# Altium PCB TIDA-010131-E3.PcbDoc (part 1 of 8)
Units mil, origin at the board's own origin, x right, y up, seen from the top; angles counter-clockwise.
Board outline 6889.76 x 5118.11 mil, 6 copper layers (Top Layer, GND Layer, Signal Layer 1, Signal Layer 2, PWR Layer, Bottom Layer), stack 58.5 mil thick; 758 components, 455 nets, 2194 pads, 1156 vias.
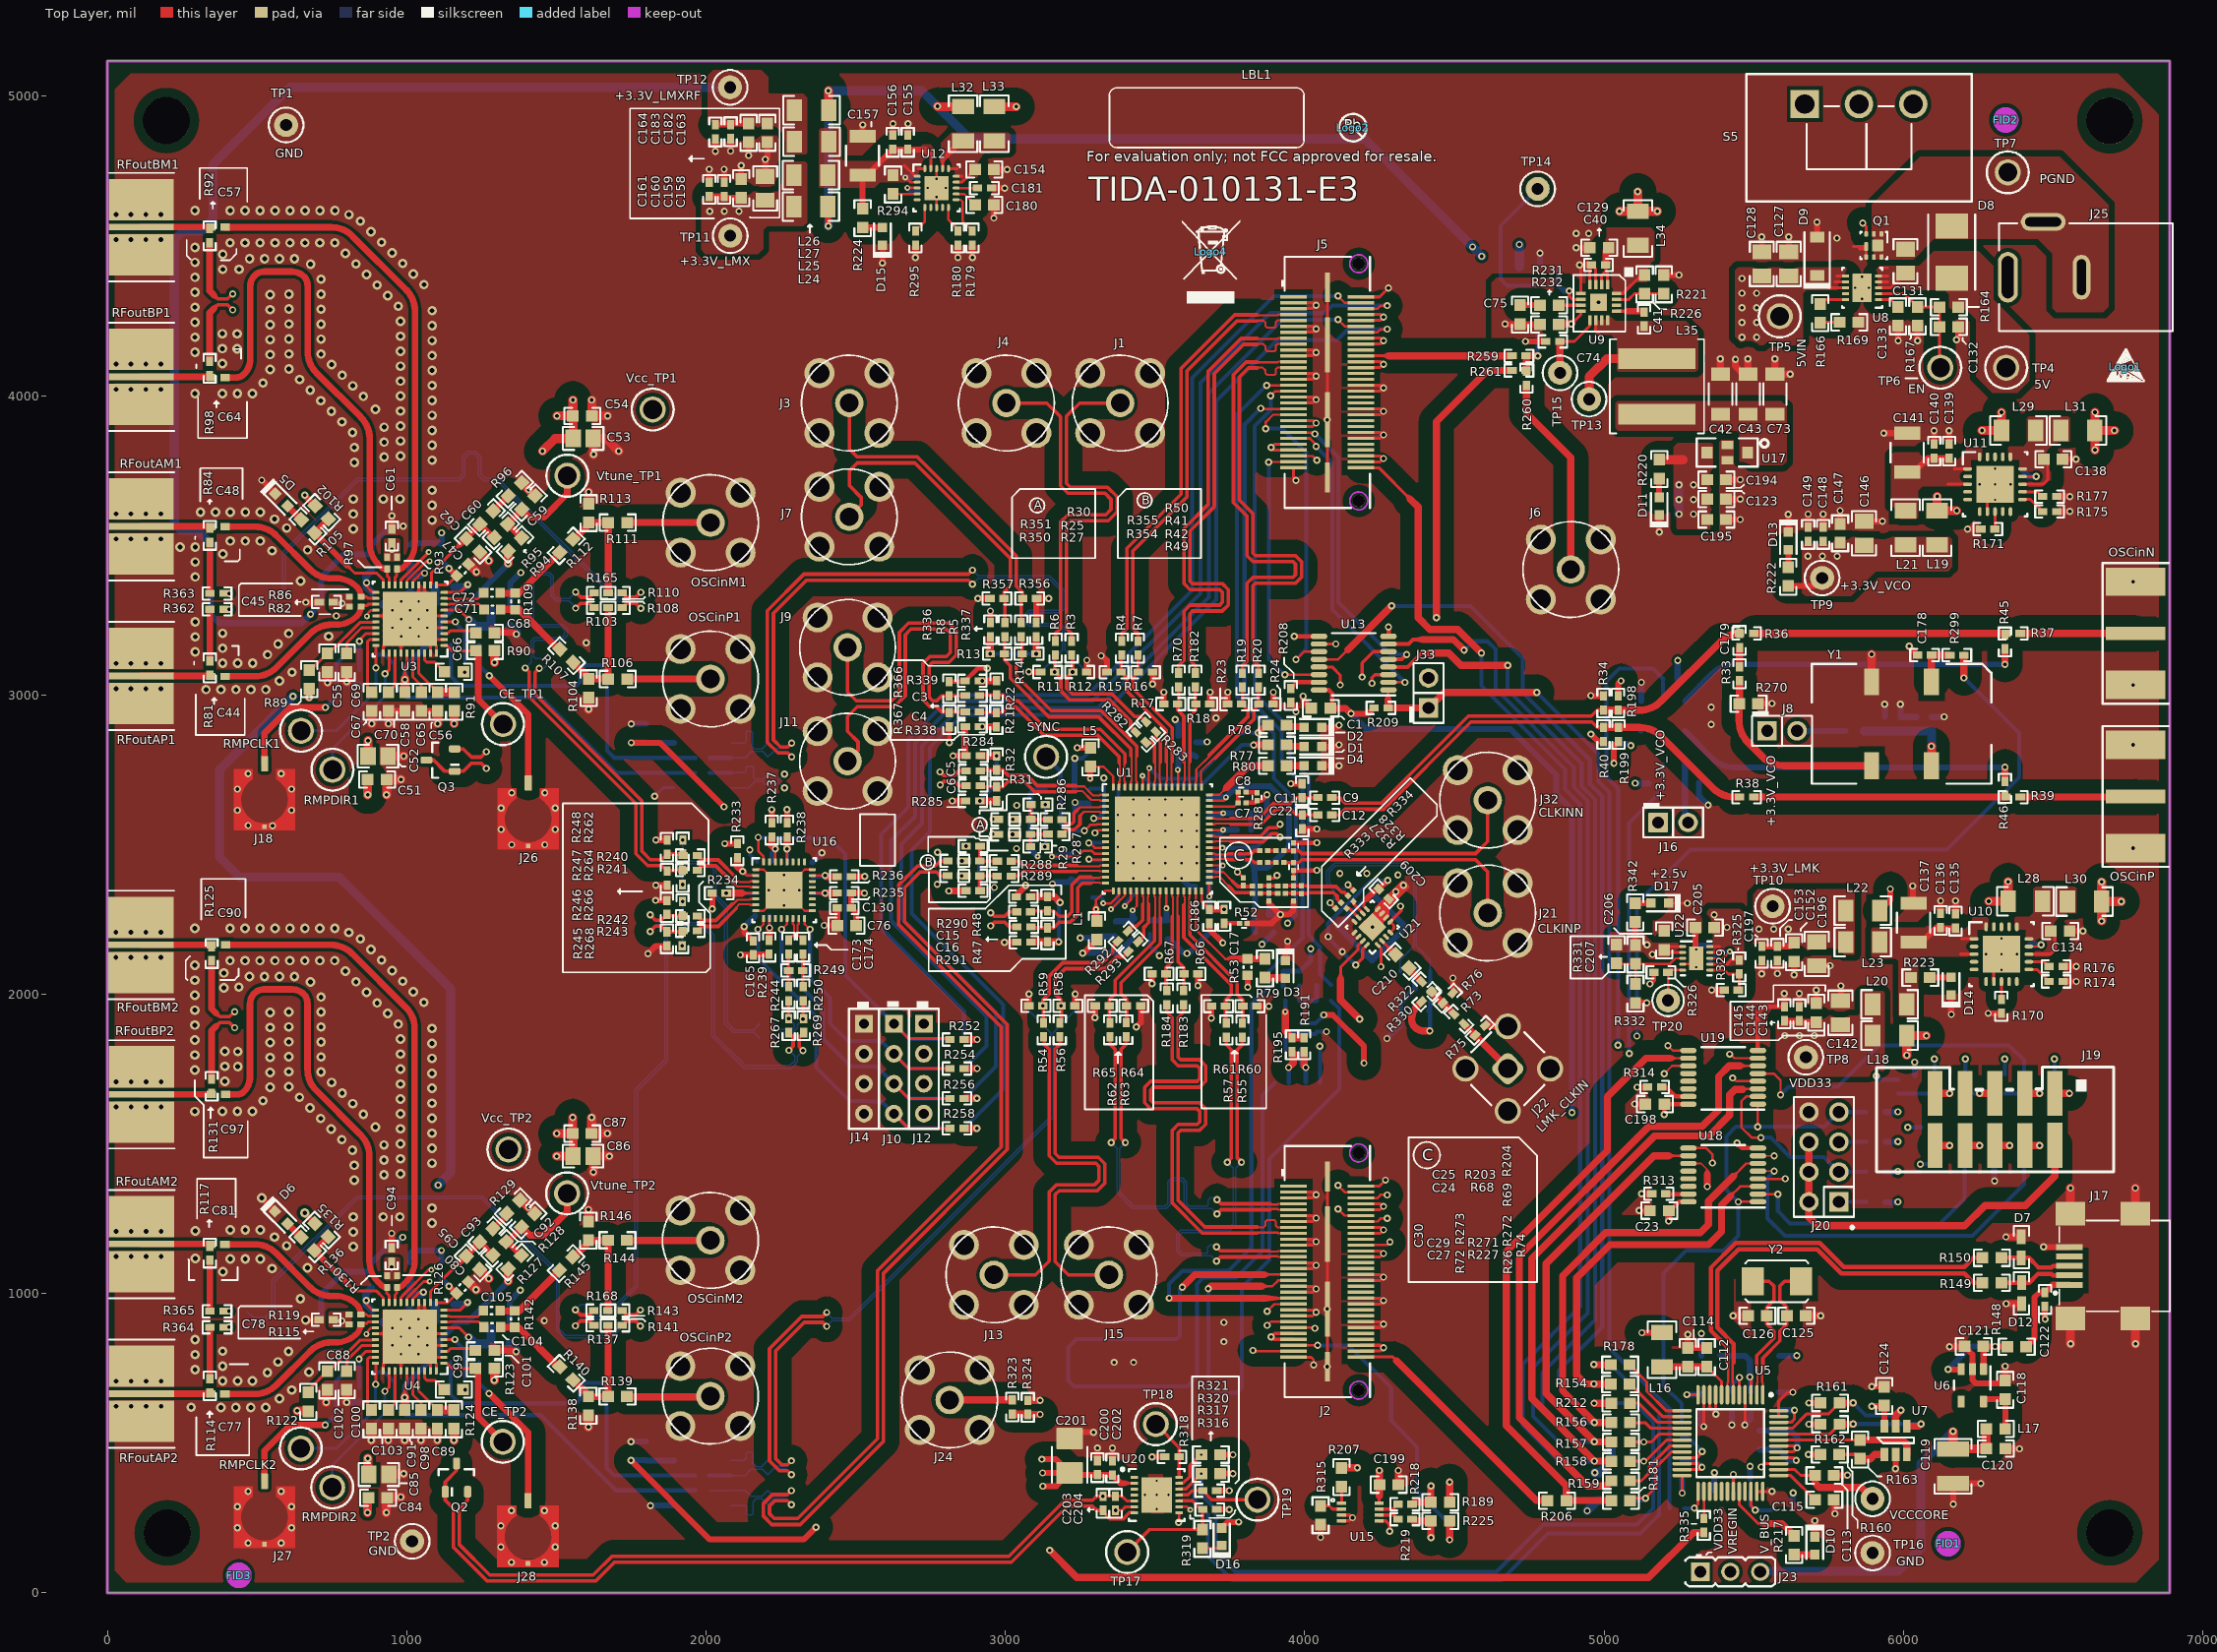
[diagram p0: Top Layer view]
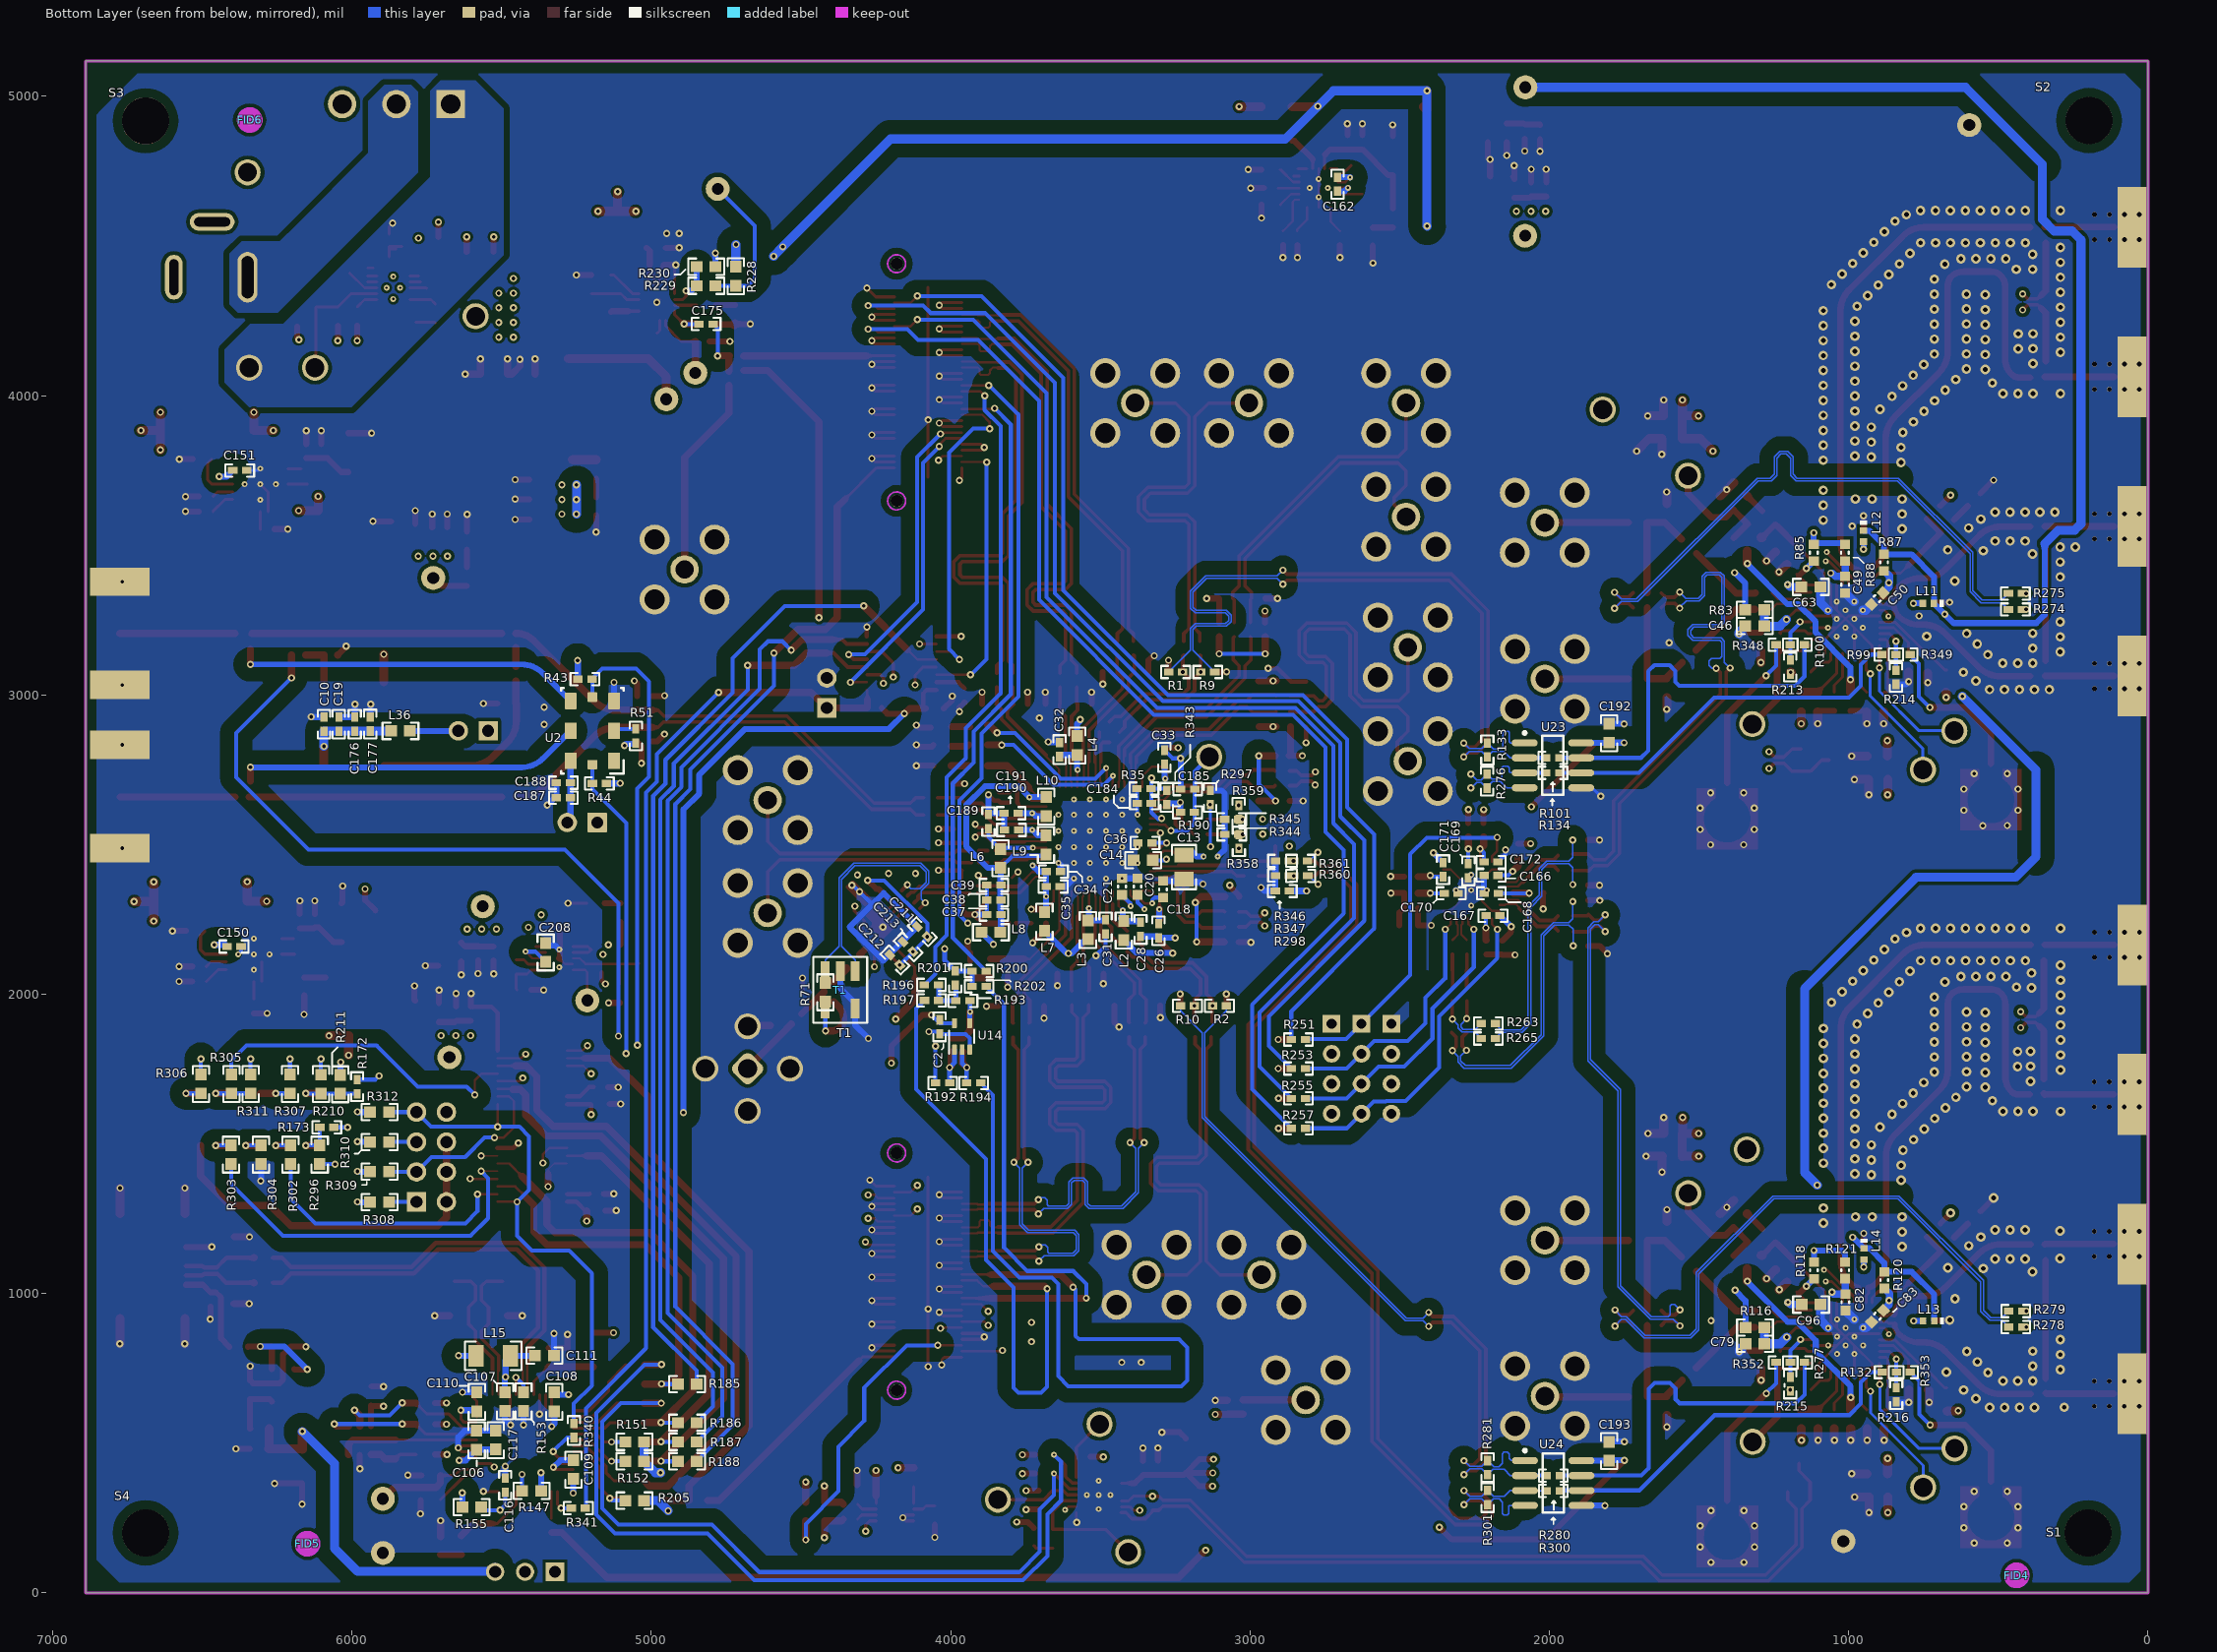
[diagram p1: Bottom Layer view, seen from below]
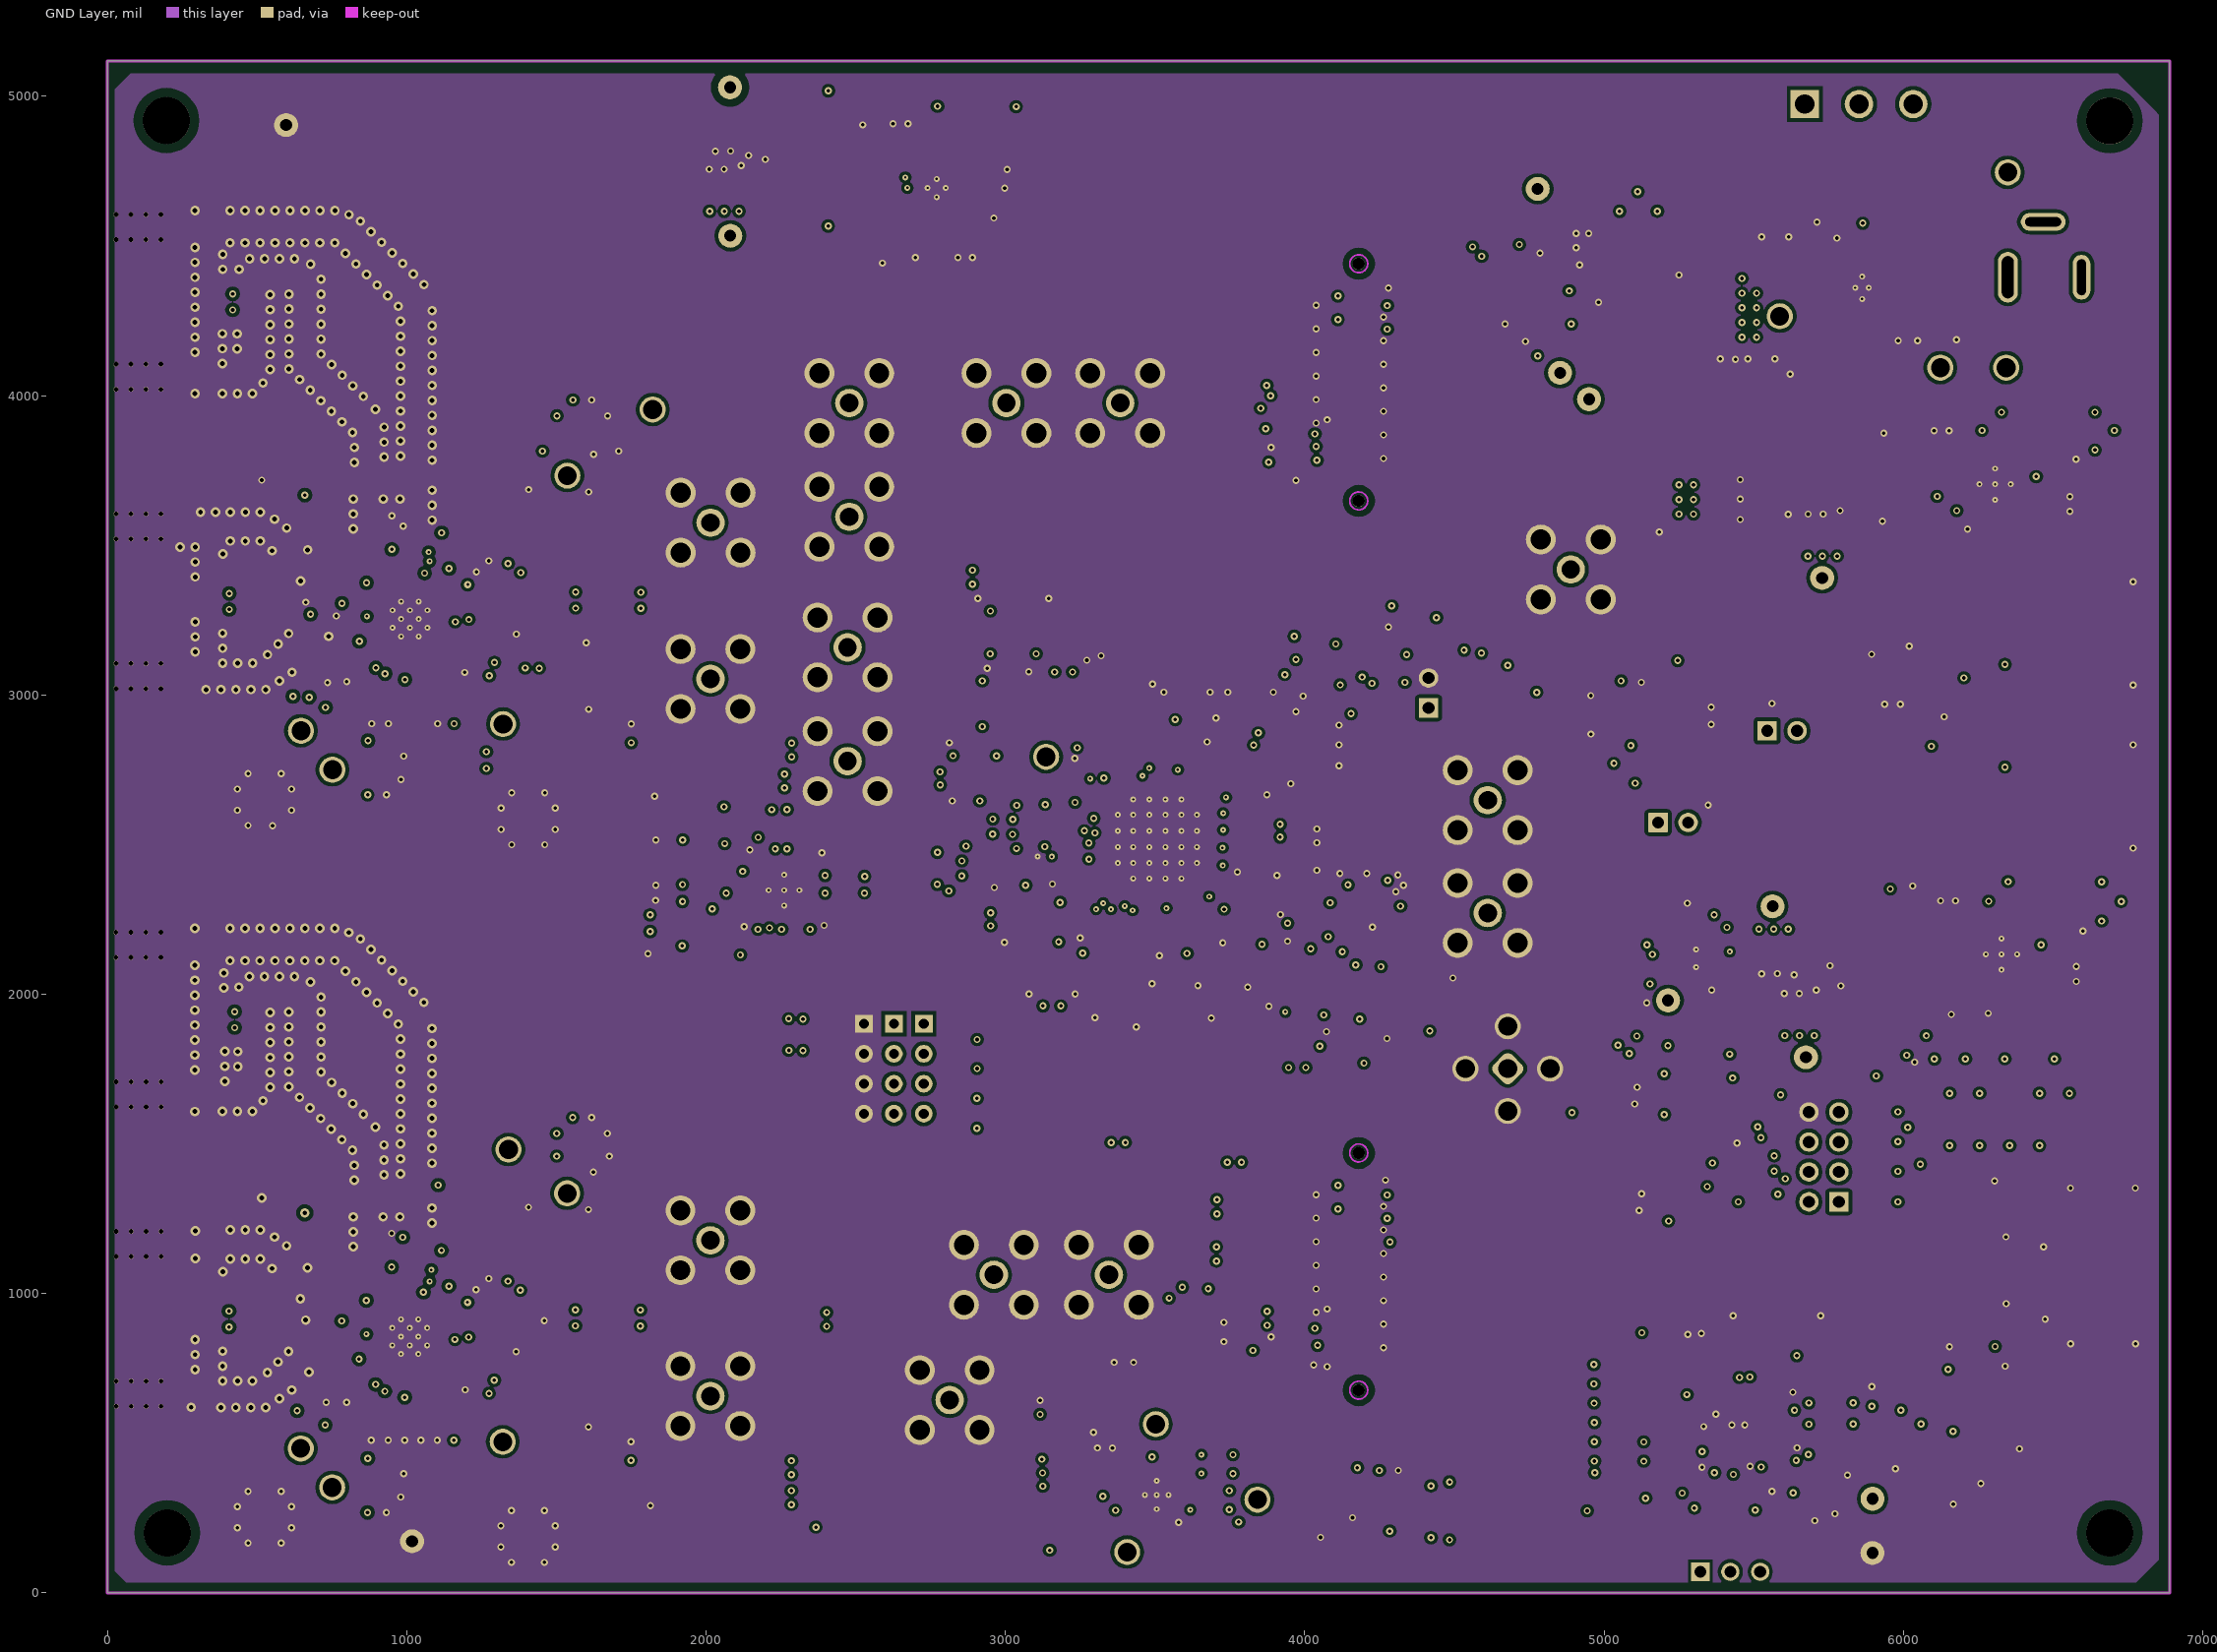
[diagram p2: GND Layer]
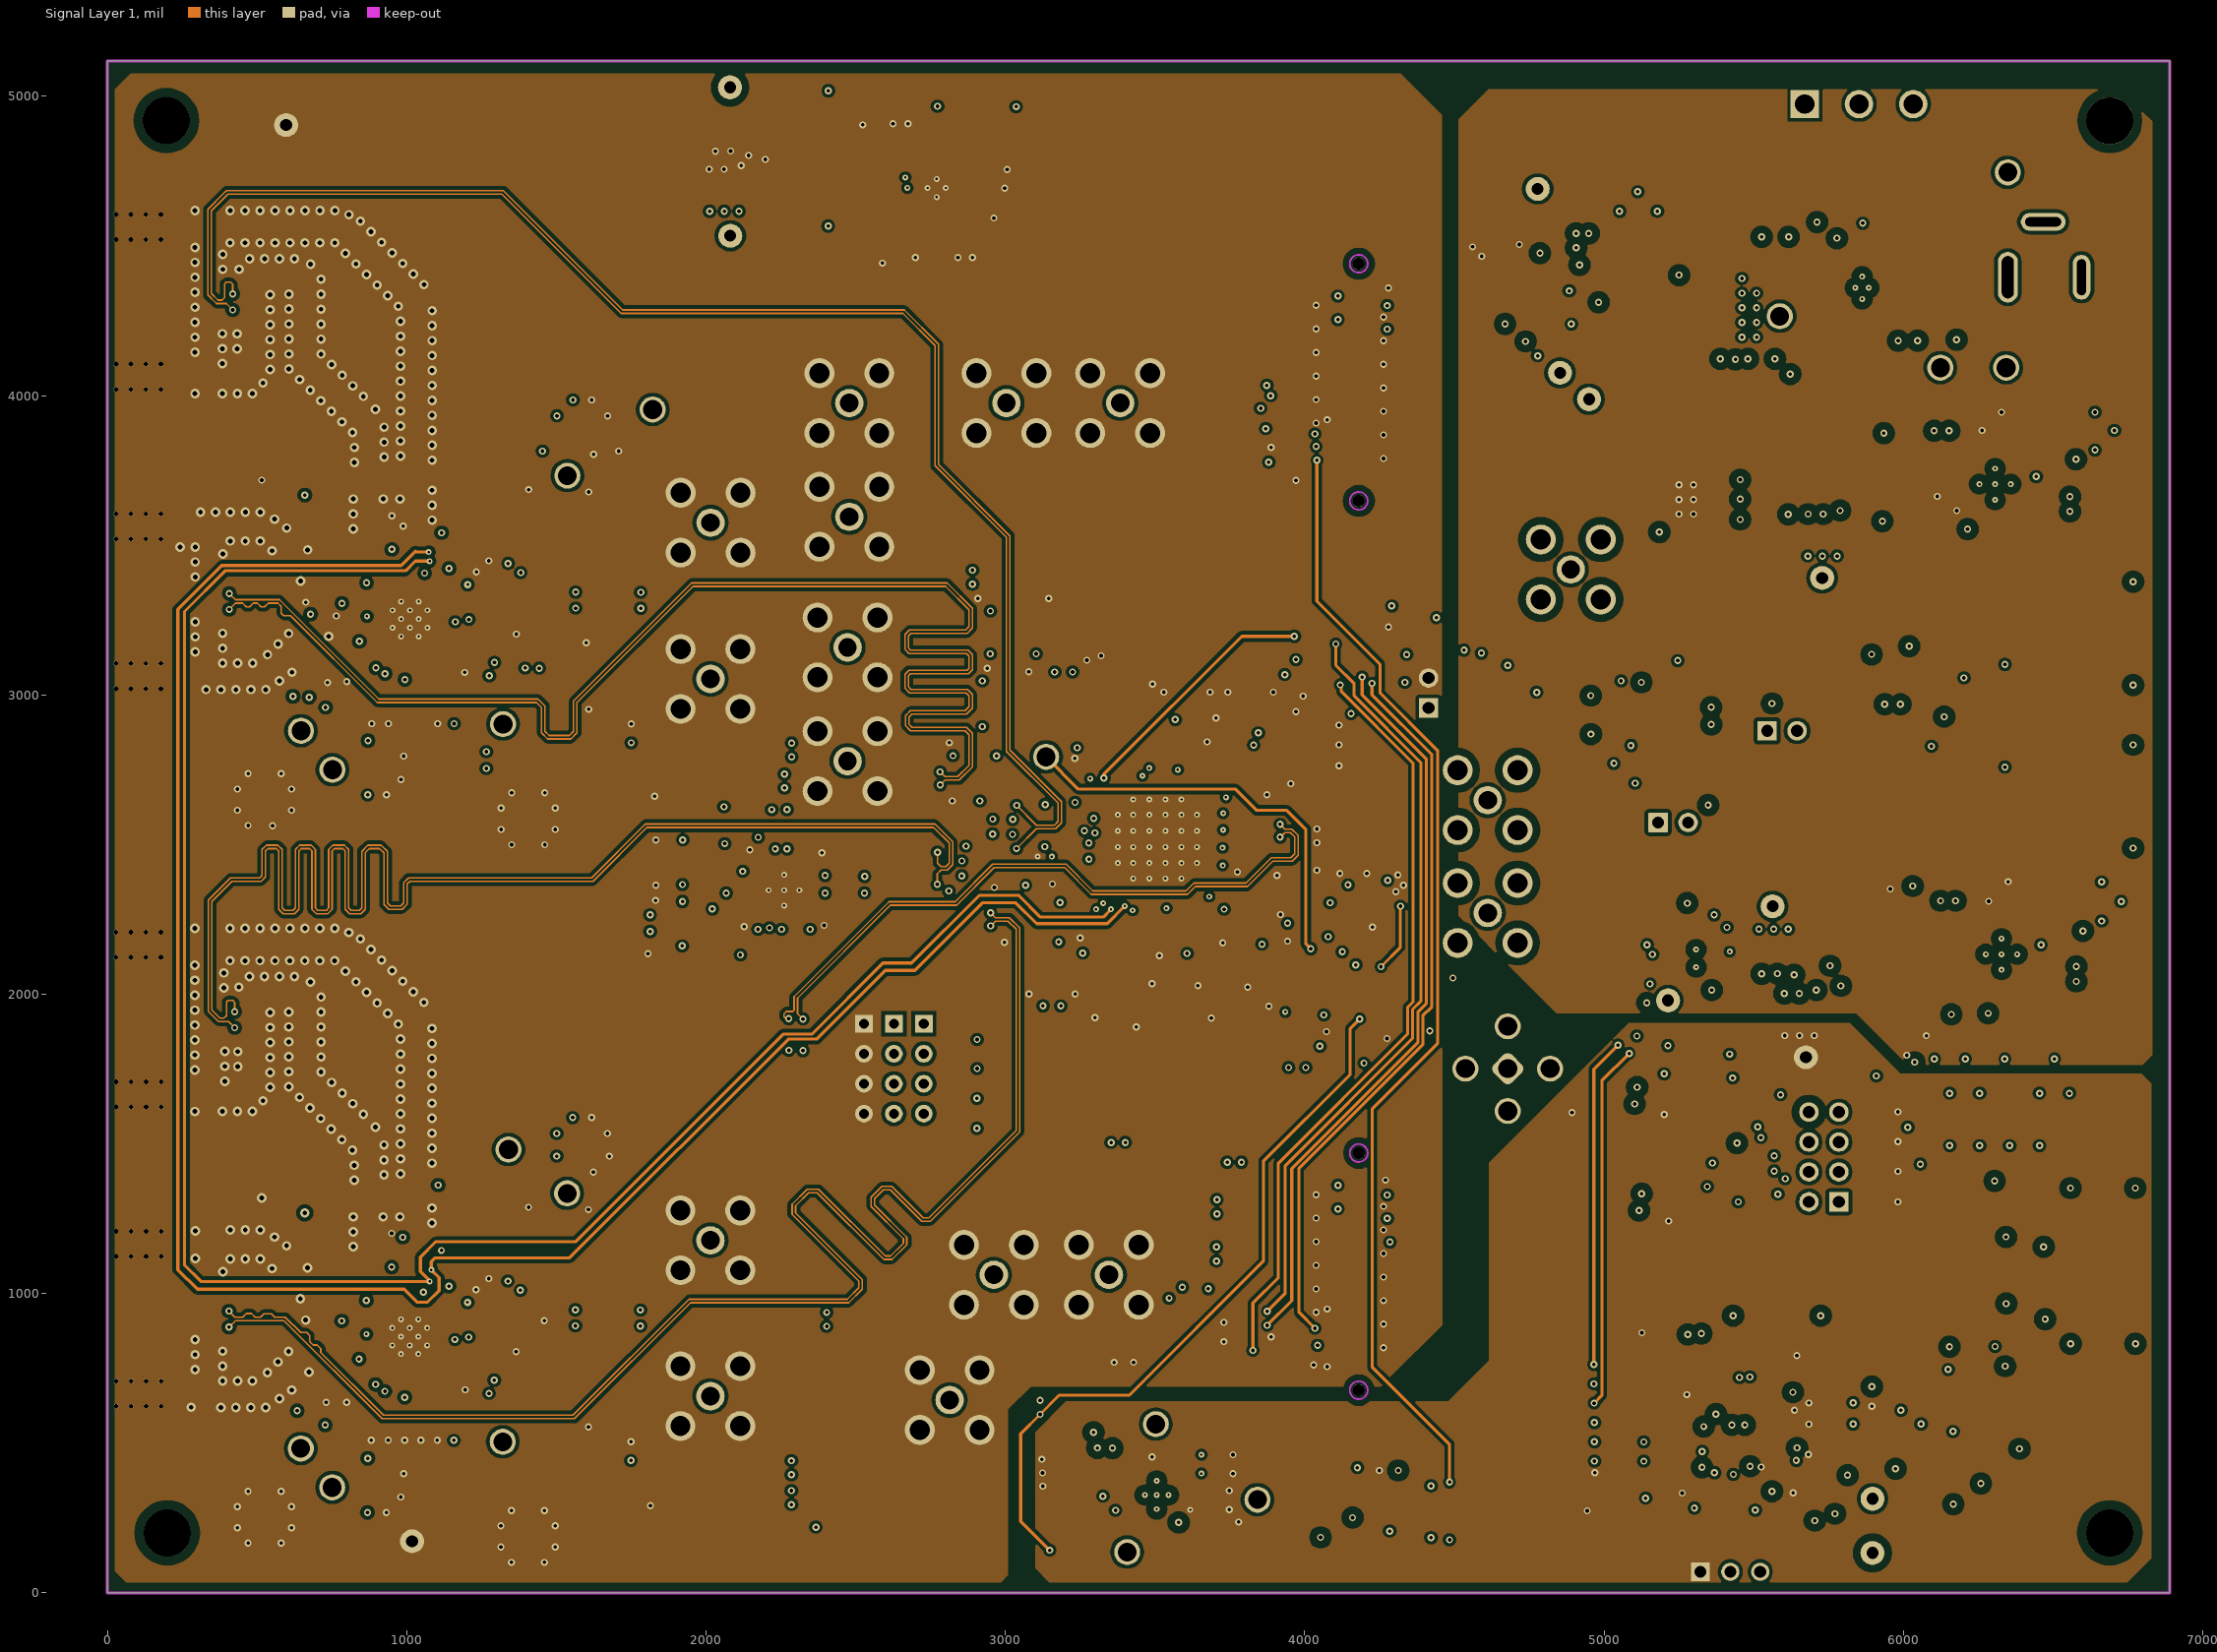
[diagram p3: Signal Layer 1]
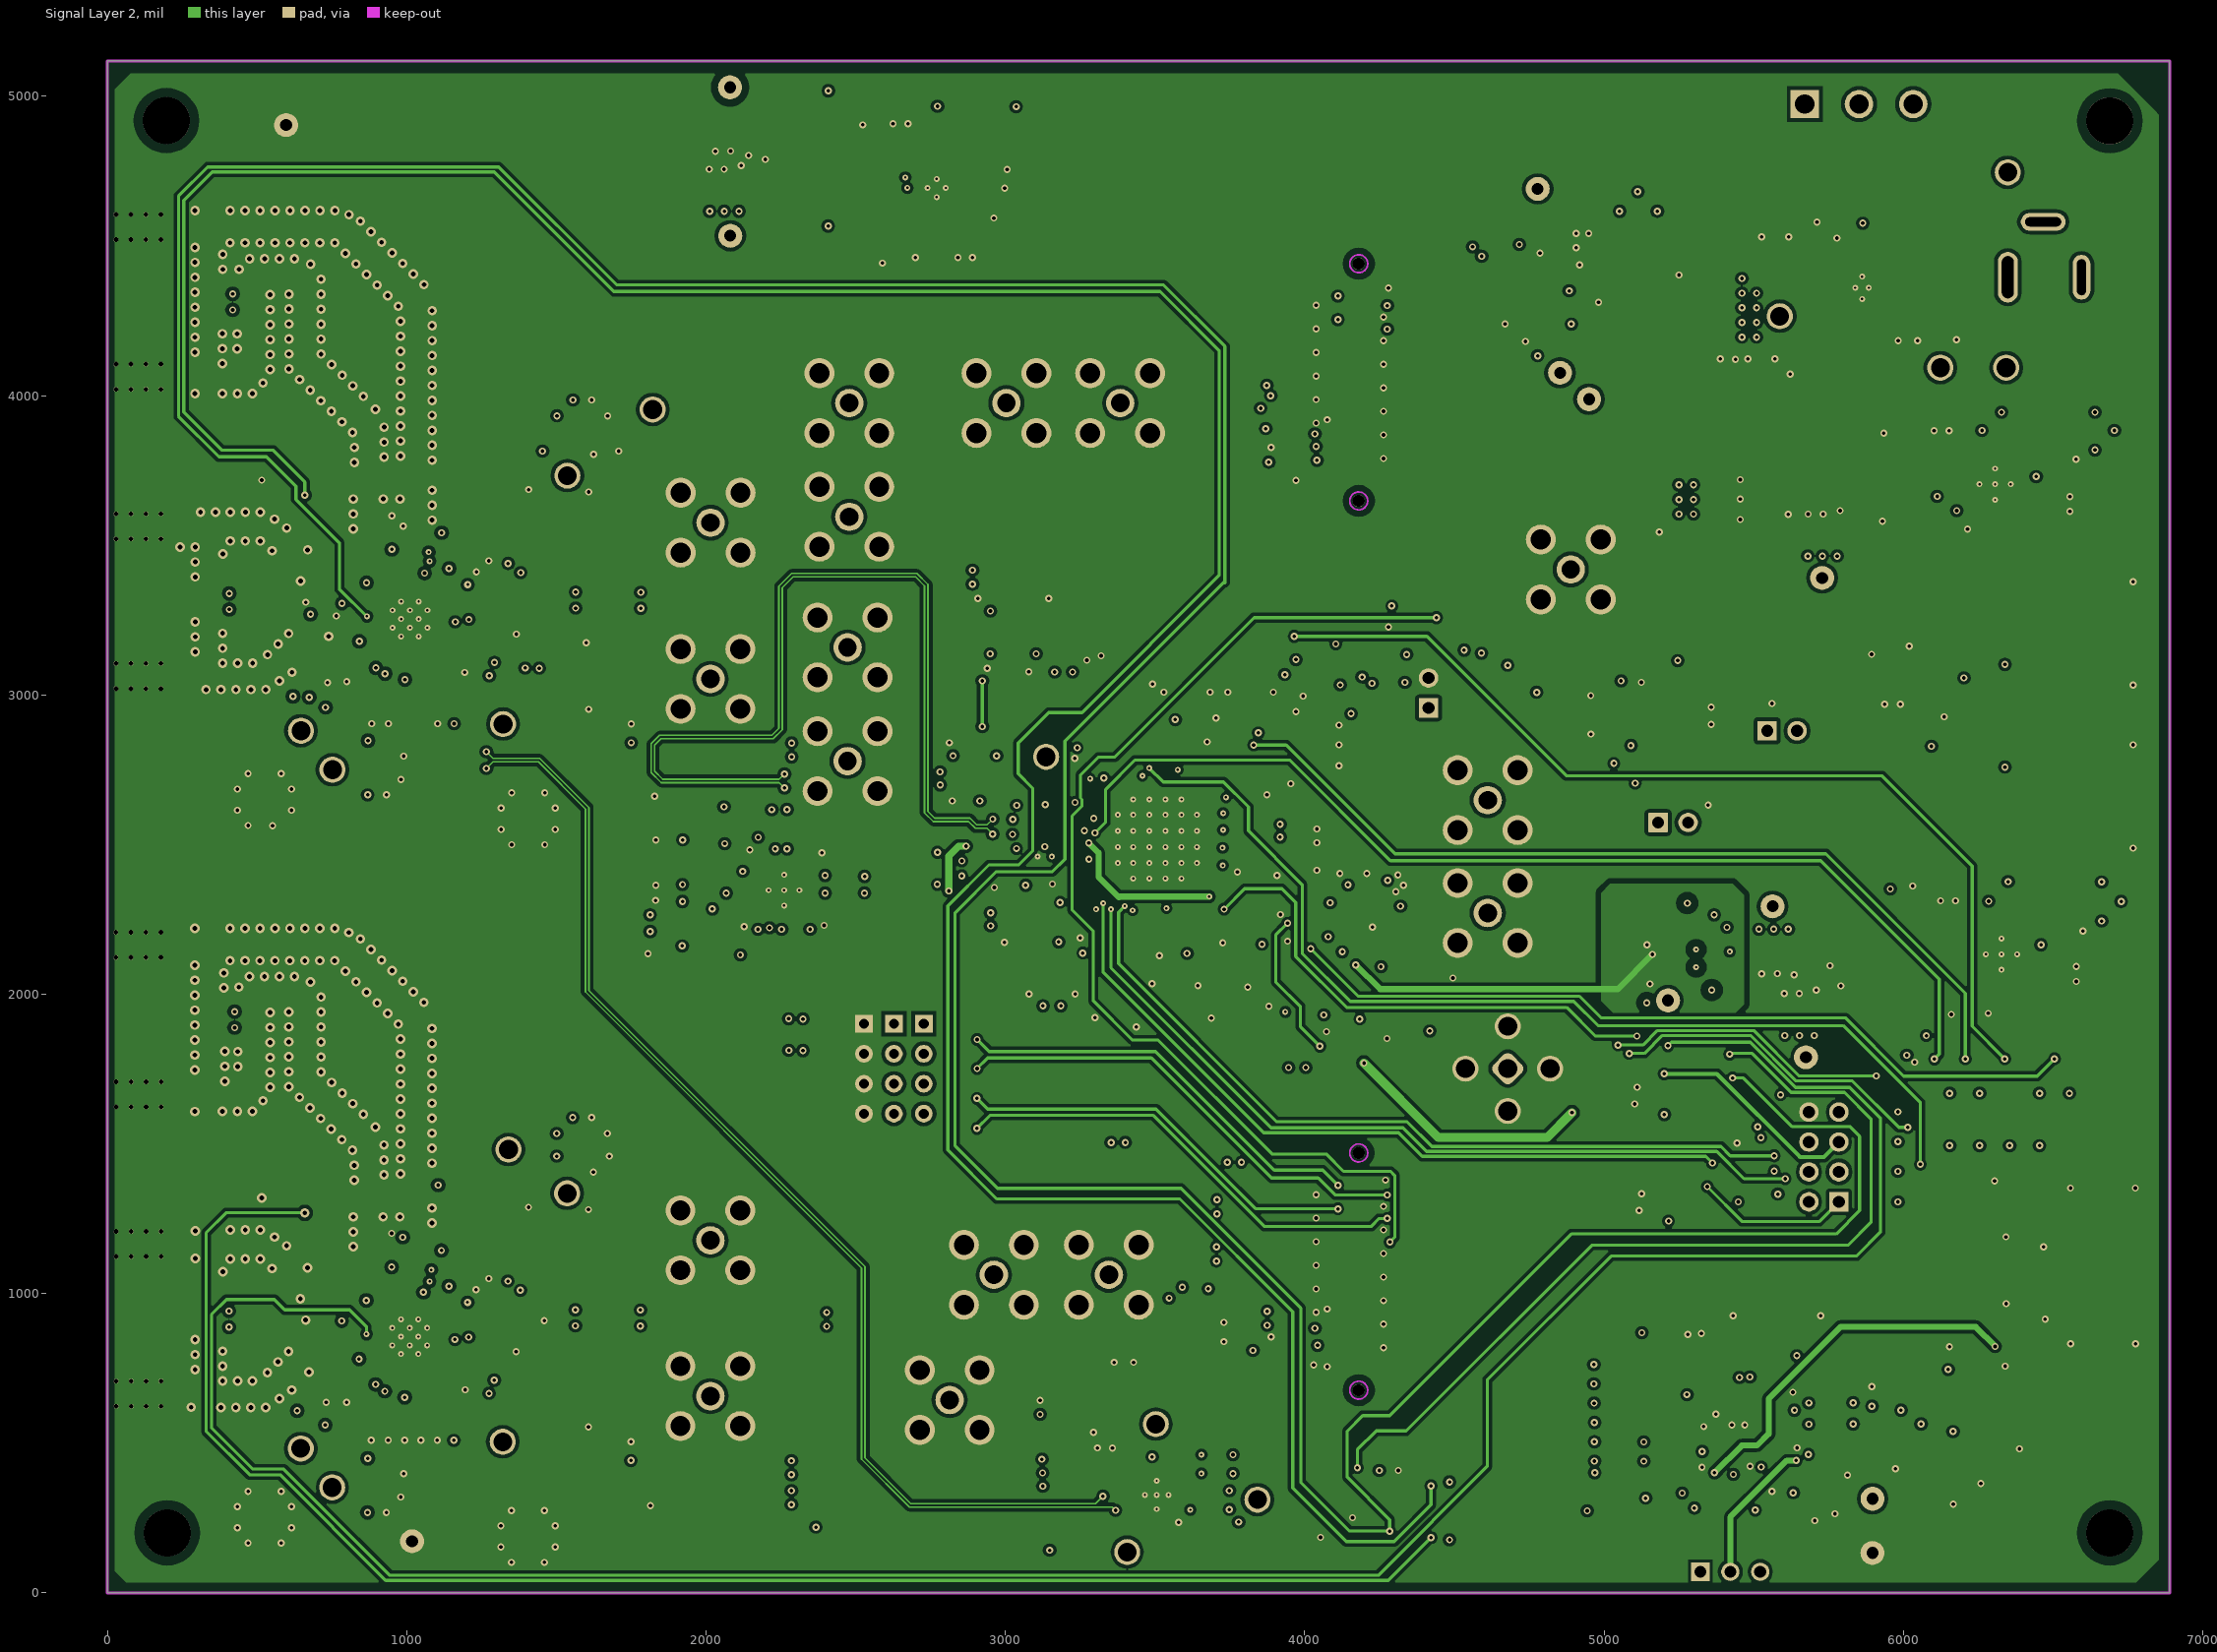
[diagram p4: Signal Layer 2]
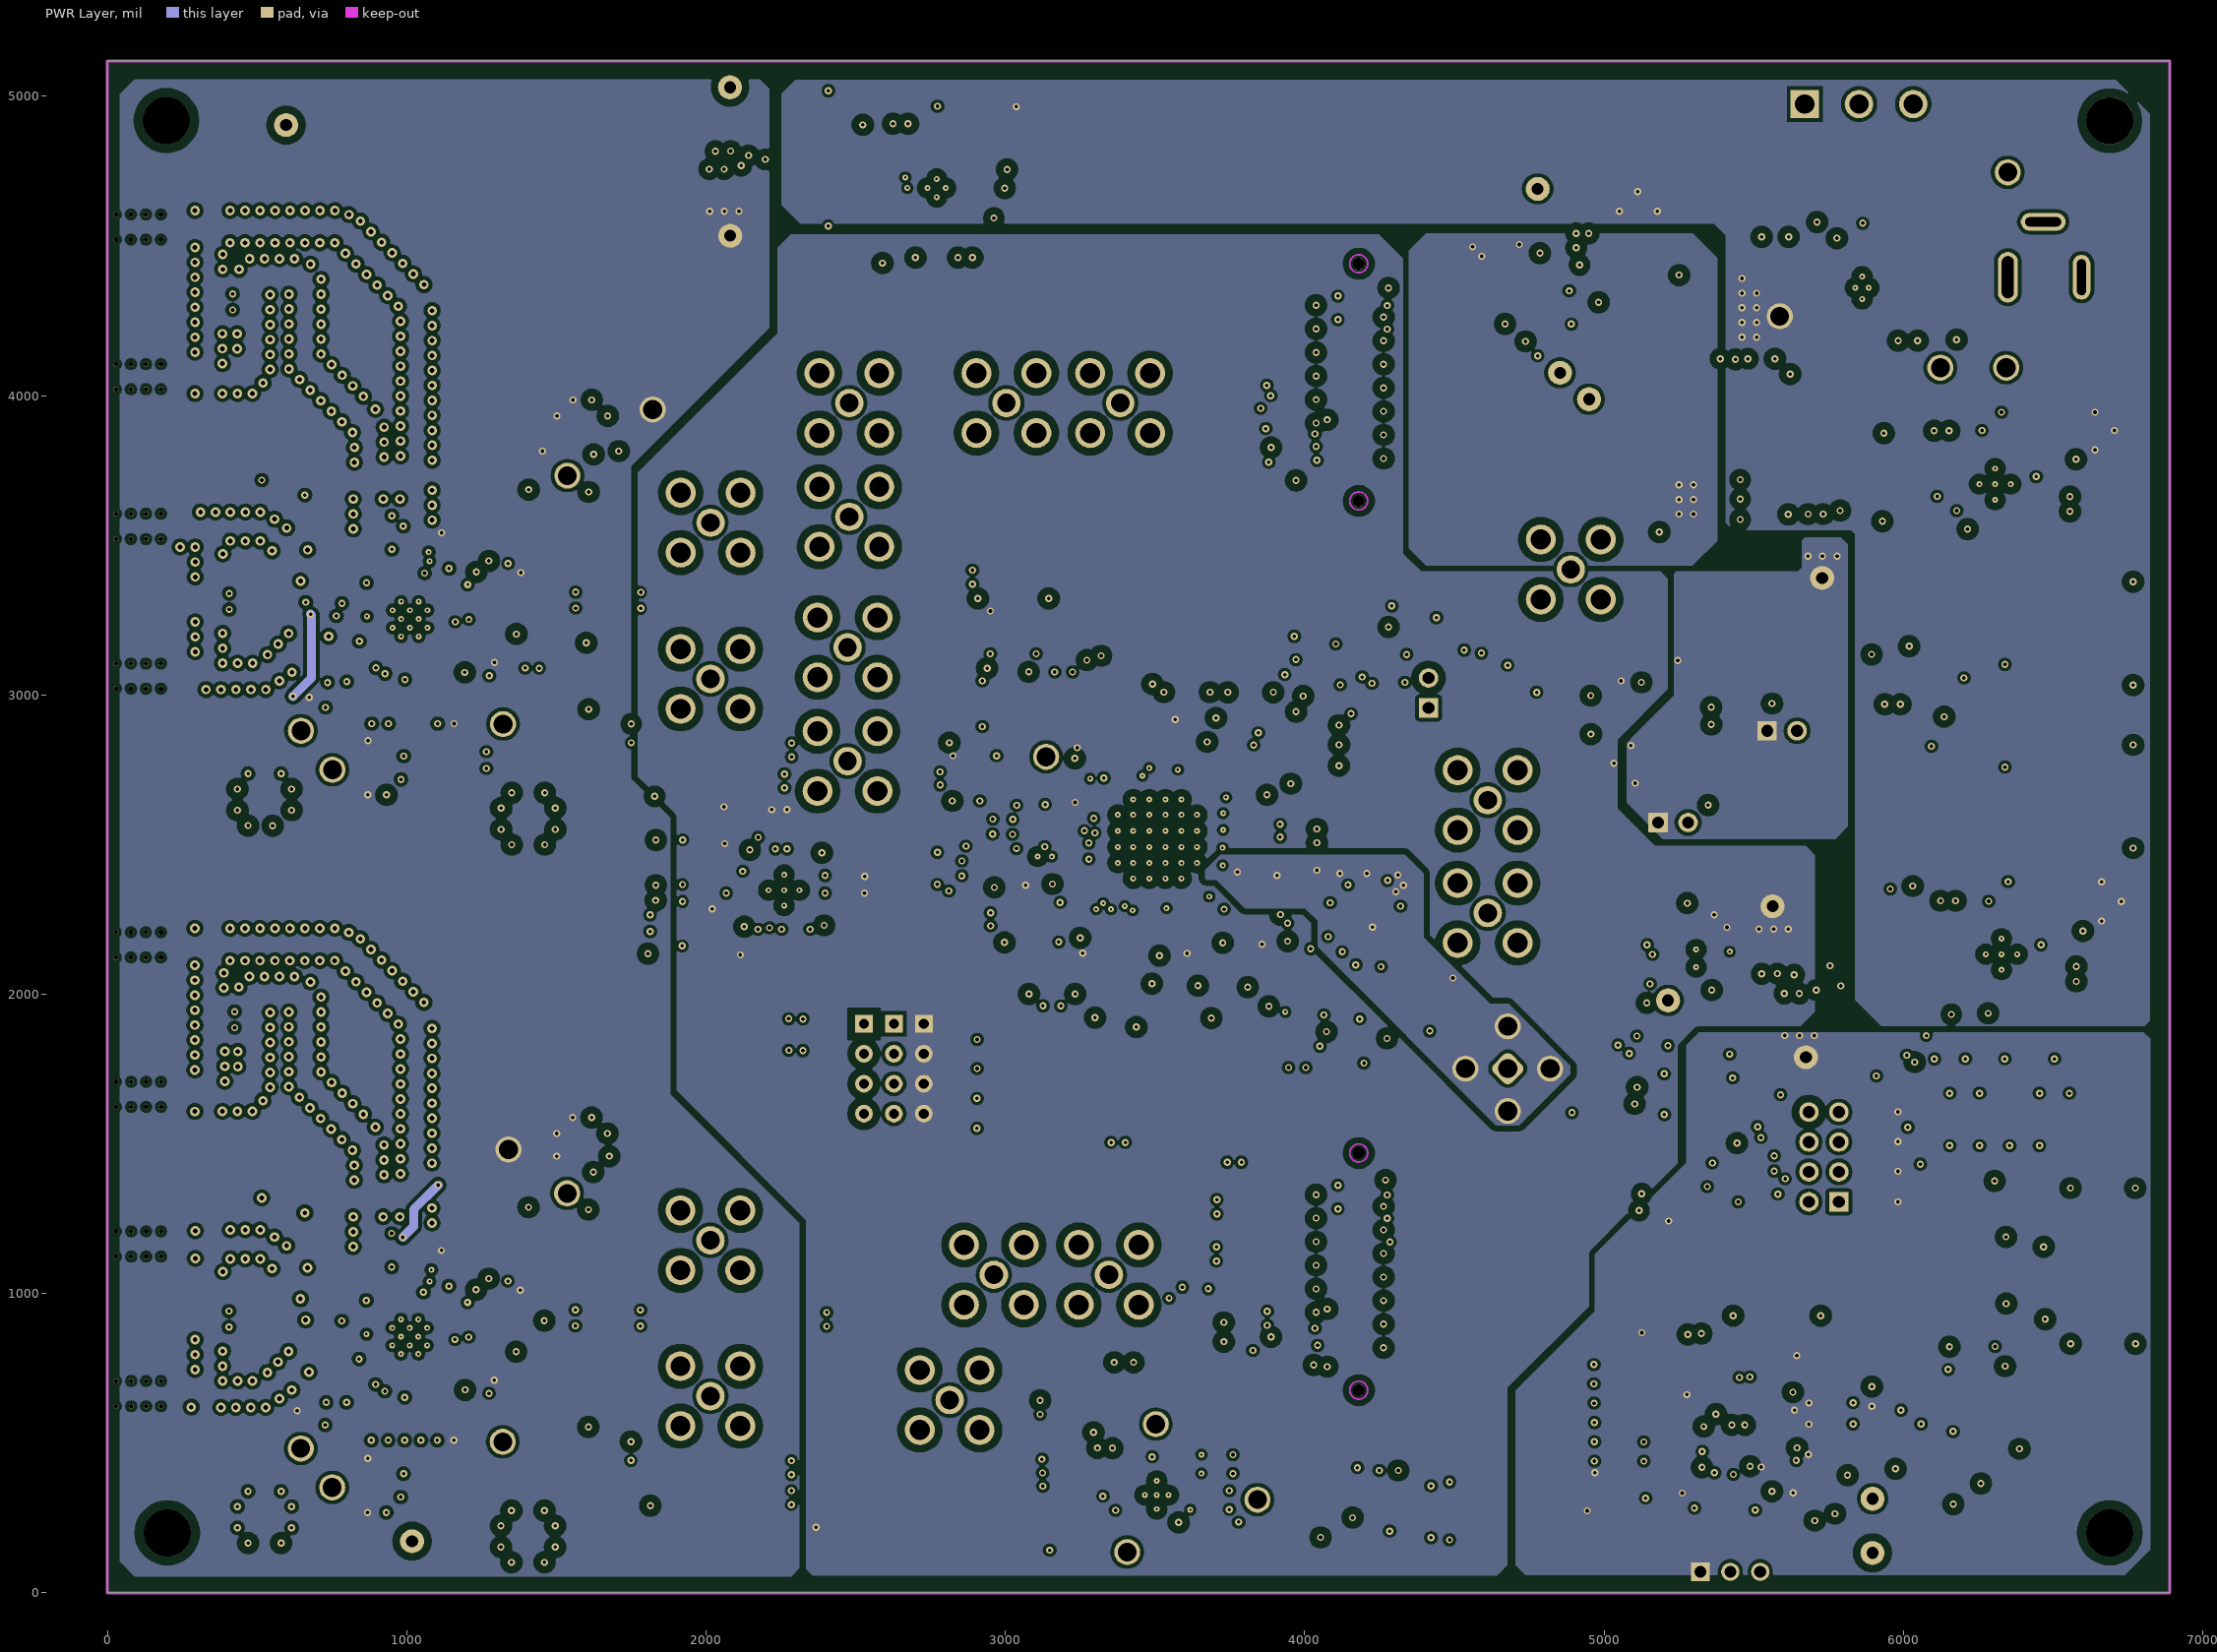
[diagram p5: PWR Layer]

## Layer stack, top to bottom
Top Solder: solder mask 0.4, Solder Resist, Dk 3.5
Top Layer: signal copper 1.4
Dielectric1: core 12, Rogers4003C, Dk 4.2
GND Layer: signal copper 0.7
Dielectric 4: prepreg 8.5, FR4 370, Dk 4.2
Signal Layer 1: signal copper 1.4
Dielectric 3: core 14.5, FR4 370, Dk 4.2
Signal Layer 2: signal copper 1.4
Dielectric 5: prepreg 8.5, FR4 370, Dk 4.2
PWR Layer: signal copper 0.7
Dielectric 2: core 8, FR4 370, Dk 4.2
Bottom Layer: signal copper 1.4
Bottom Solder: solder mask 0.4, Solder Resist, Dk 3.5

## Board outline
0,0 0,5118.11 6889.76,5118.11 6889.76,0

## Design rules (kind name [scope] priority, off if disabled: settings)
AcuteAngle [All] p1: minimum=4.50000000000000E+0001 checktracksonly=FALSE
AssemblyTestPointUsage [All] p1: valid=2
Clearance PGND [InNet('PGND') vs IsTrack] p1: gap=10 ignorepadtopadclearanceinfootprint=FALSE except(0: Arc-Hole Track-Hole SMDPad-Hole THPad-Hole Via-Hole Fill-Hole Poly-Hole Region-Hole Text-Hole)
Clearance 5v [InNet('5V') and InPolygon vs isvia] p2: gap=8 ignorepadtopadclearanceinfootprint=FALSE except(0: Arc-Hole Track-Hole SMDPad-Hole THPad-Hole Via-Hole Fill-Hole Poly-Hole Region-Hole Text-Hole)
Clearance Clearance_LMx2 [WithinRoom('TIDA-010131-E3_LMX2594R_2') vs InPoly] p3: gap=12 ignorepadtopadclearanceinfootprint=FALSE except(0: Arc-Hole Track-Hole SMDPad-Hole THPad-Hole Via-Hole Fill-Hole Poly-Hole Region-Hole Text-Hole)
Clearance Clearance_LMx1 [WithinRoom('TIDA-01021_E3_LMX2594R_1') vs InPoly] p4: gap=12 ignorepadtopadclearanceinfootprint=FALSE except(0: Arc-Hole Track-Hole SMDPad-Hole THPad-Hole Via-Hole Fill-Hole Poly-Hole Region-Hole Text-Hole)
Clearance Clearance_top [OnLayer('Top Layer') vs InNet('GND')] p5: gap=6 ignorepadtopadclearanceinfootprint=FALSE except(0: Arc-Hole Track-Hole SMDPad-Hole THPad-Hole Via-Hole Fill-Hole Poly-Hole Region-Hole Text-Hole; 12: Arc-Poly THPad-Poly Fill-Poly; 20: SMDPad-Poly Poly-Poly; 48: Track-Poly Via-Poly)
Clearance Clearance_bottom [OnLayer('Bottom Layer') vs InNet('GND')] p6: gap=6 ignorepadtopadclearanceinfootprint=FALSE except(0: Arc-Hole Track-Hole SMDPad-Hole THPad-Hole Via-Hole Fill-Hole Poly-Hole Region-Hole Text-Hole; 12: Arc-Poly THPad-Poly Fill-Poly; 20: SMDPad-Poly Poly-Poly; 48: Track-Poly Via-Poly)
Clearance Clearance_Poly [InPolygon vs InPolygon] p7: gap=20 ignorepadtopadclearanceinfootprint=FALSE except(0: Arc-Hole Track-Hole SMDPad-Hole THPad-Hole Via-Hole Fill-Hole Poly-Hole Region-Hole Text-Hole)
Clearance Clearance_POLYALLTOP [InNet('GND') vs InPoly] p8: gap=25 ignorepadtopadclearanceinfootprint=FALSE except(0: Arc-Hole Track-Hole SMDPad-Hole THPad-Hole Via-Hole Fill-Hole Poly-Hole Region-Hole Text-Hole)
Clearance Clearance_3.3vRF [InNet('+3.3V_LMXRF') vs InPoly] p9: gap=25 ignorepadtopadclearanceinfootprint=FALSE except(0: Arc-Hole Track-Hole SMDPad-Hole THPad-Hole Via-Hole Fill-Hole Poly-Hole Region-Hole Text-Hole)
Clearance Clearance_diff [InAnyDifferentialPair vs InAnyDifferentialPair] p10: gap=6 ignorepadtopadclearanceinfootprint=FALSE except(0: Arc-Hole Track-Hole SMDPad-Hole THPad-Hole Via-Hole Fill-Hole Poly-Hole Region-Hole Text-Hole; 4.25: Arc-Track Track-Track)
Clearance Clearance_keepout [IsKeepOut vs InPolygon] p11: gap=20 ignorepadtopadclearanceinfootprint=FALSE except(0: Arc-Hole Track-Hole SMDPad-Hole THPad-Hole Via-Hole Fill-Hole Poly-Hole Region-Hole Text-Hole)
Clearance "Clearance_MH to Copper" [InPadClass('MH') vs InPolygon] p12: gap=30 ignorepadtopadclearanceinfootprint=FALSE except(0: Arc-Hole Track-Hole SMDPad-Hole THPad-Hole Via-Hole Fill-Hole Poly-Hole Region-Hole Text-Hole)
Clearance "Clearance_Poly to All" [InPoly] p13: gap=12 ignorepadtopadclearanceinfootprint=FALSE except(0: Arc-Hole Track-Hole SMDPad-Hole THPad-Hole Via-Hole Fill-Hole Poly-Hole Region-Hole Text-Hole; 10: Via-Poly)
Clearance "Via to Via" [IsVia vs IsVia] p14: gap=8 ignorepadtopadclearanceinfootprint=FALSE except(0: Arc-Hole Track-Hole SMDPad-Hole THPad-Hole Via-Hole Fill-Hole Poly-Hole Region-Hole Text-Hole)
Clearance "Via 2 SMD PAD" [IsVia vs IsSMTPin] p15: gap=8 ignorepadtopadclearanceinfootprint=FALSE except(0: Arc-Hole Track-Hole SMDPad-Hole THPad-Hole Via-Hole Fill-Hole Poly-Hole Region-Hole Text-Hole)
Clearance Clearance_PadClass [InPadClass('U1') vs InPadClass('U1')] p16: gap=7.8 ignorepadtopadclearanceinfootprint=FALSE except(0: Arc-Hole Track-Hole SMDPad-Hole THPad-Hole Via-Hole Fill-Hole Poly-Hole Region-Hole Text-Hole)
Clearance [All] p17: gap=6 ignorepadtopadclearanceinfootprint=FALSE except(0: Arc-Arc Arc-SMDPad Arc-Hole Track-Hole SMDPad-Hole THPad-Hole Via-Hole Fill-Hole Poly-Hole Region-Hole Text-Hole)
ComponentClearance ComponentClearance_Shunt [InComponentClass('Header') vs InComponentClass('Shunt')] p1: gap=0 collisioncheckmode=3 verticalgap=0 showdistances=FALSE
ComponentClearance ComponentClearance_Logo [InComponentClass('Logo')] p2: gap=50 collisioncheckmode=3 verticalgap=10 showdistances=FALSE
ComponentClearance ComponentClearance_ScrewToNut [(HasFootprint('NY PMS 440 0025 PH')) vs (HasFootprint('Keystone_1902C'))] p3: gap=5 collisioncheckmode=3 verticalgap=10 showdistances=FALSE
ComponentClearance ComponentClearance_MountingHoles [InComponentClass('Mounting Holes')] p4: gap=250 collisioncheckmode=3 verticalgap=100000 showdistances=FALSE
ComponentClearance ComponentClearance_SmallPassives [HasFootprint('0201*') or HasFootprint('0402*') or HasFootprint('0508') or HasFootprint('0603*') or HasFootprint('0612') or HasFootprint('0805*') or HasFootprint('0815*') or HasFootprint('0830*') or HasFootprint('1206*') or HasFootprint('1210*') or HasFootprint('1808*') or HasFootprint('1812*') or HasFootprint('1825*') or HasFootprint('2010*') or HasFootprint('2220*') or HasFootprint('2225*') or HasFootprint('2512*') or HasFootprint('2728*') or HasFootprint('3518*') vs HasFootprint('0201*') or HasFootprint('0402*') or HasFootprint('0508') or HasFootprint('0603*') or HasFootprint('0612') or HasFootprint('0805*') or HasFootprint('0815*') or HasFootprint('0830*') or HasFootprint('1206*') or HasFootprint('1210*') or HasFootprint('1808*') or HasFootprint('1812*') or HasFootprint('1825*') or HasFootprint('2010*') or HasFootprint('2220*') or HasFootprint('2225*') or HasFootprint('2512*') or HasFootprint('2728*') or HasFootprint('3518*')] p5: gap=20 collisioncheckmode=3 verticalgap=10 showdistances=FALSE
ComponentClearance ComponentClearance_THtoSMT [IsThruComponent vs IsSMTComponent] p6: gap=100 collisioncheckmode=3 verticalgap=30 showdistances=FALSE
ComponentClearance ComponentClearance_THtoTH [IsThruComponent vs IsThruComponent] p7: gap=118.11 collisioncheckmode=3 verticalgap=30 showdistances=FALSE
ComponentClearance [All] p8: gap=40 collisioncheckmode=3 verticalgap=10 showdistances=FALSE
DiffPairsRouting DiffPairsRouting_CPW_100OHM [InDifferentialPairClass('CPW_100OHM')] p1: maxlimit=8 minlimit=8 mostfreqgap=8 toplayer_minwidth=8 toplayer_maxwidth=12 toplayer_prefwidth=12 midlayer1_mingap=0 midlayer1_maxgap=0 midlayer1_prefgap=0 midlayer1_minwidth=0 midlayer1_maxwidth=0 midlayer1_prefwidth=0 midlayer2_mingap=0 midlayer2_maxgap=0 midlayer2_prefgap=0 midlayer2_minwidth=0 midlayer2_maxwidth=0 midlayer2_prefwidth=0 midlayer3_mingap=0 midlayer3_maxgap=0 midlayer3_prefgap=0 midlayer3_minwidth=0 midlayer3_maxwidth=0 midlayer3_prefwidth=0 midlayer4_mingap=0 midlayer4_maxgap=0 midlayer4_prefgap=0 midlayer4_minwidth=0 midlayer4_maxwidth=0 midlayer4_prefwidth=0 bottomlayer_mingap=0 bottomlayer_maxgap=0 bottomlayer_prefgap=0 bottomlayer_minwidth=0 bottomlayer_maxwidth=0 bottomlayer_prefwidth=0 maxuncoupledlength=500
DiffPairsRouting DiffPair_DiffPairsRouting_USB [InDifferentialPairClass('USB_DIFF_90OHM')] p2: maxlimit=7 minlimit=4.5 mostfreqgap=5 toplayer_prefgap=7 toplayer_minwidth=8 toplayer_maxwidth=15 toplayer_prefwidth=15 midlayer1_mingap=0 midlayer1_maxgap=0 midlayer1_prefgap=0 midlayer1_minwidth=0 midlayer1_maxwidth=0 midlayer1_prefwidth=0 midlayer2_mingap=5 midlayer2_maxgap=5 midlayer2_minwidth=6.5 midlayer2_maxwidth=6.5 midlayer2_prefwidth=6.5 midlayer3_mingap=5 midlayer3_maxgap=5 midlayer3_minwidth=6.5 midlayer3_maxwidth=6.5 midlayer3_prefwidth=6.5 midlayer4_mingap=0 midlayer4_maxgap=0 midlayer4_prefgap=0 midlayer4_minwidth=0 midlayer4_maxwidth=0 midlayer4_prefwidth=0 bottomlayer_mingap=5 bottomlayer_maxgap=5 bottomlayer_minwidth=7 bottomlayer_maxwidth=7 bottomlayer_prefwidth=7 maxuncoupledlength=500
DiffPairsRouting DiffPairsRouting_100OHM [InDifferentialPairClass('100OHM')] p3: maxlimit=8 minlimit=4.25 mostfreqgap=6 toplayer_mingap=8 toplayer_prefgap=8 toplayer_minwidth=7 toplayer_maxwidth=12 toplayer_prefwidth=12 midlayer1_mingap=0 midlayer1_maxgap=0 midlayer1_prefgap=0 midlayer1_minwidth=0 midlayer1_maxwidth=0 midlayer1_prefwidth=0 midlayer2_mingap=6 midlayer2_maxgap=6 midlayer2_minwidth=5.5 midlayer2_maxwidth=5.5 midlayer2_prefwidth=5.5 midlayer3_mingap=6 midlayer3_maxgap=6 midlayer3_minwidth=5.5 midlayer3_maxwidth=5.5 midlayer3_prefwidth=5.5 midlayer4_mingap=0 midlayer4_maxgap=0 midlayer4_prefgap=0 midlayer4_minwidth=0 midlayer4_maxwidth=0 midlayer4_prefwidth=0 bottomlayer_maxgap=4.25 bottomlayer_prefgap=4.25 bottomlayer_minwidth=4.25 bottomlayer_maxwidth=4.25 bottomlayer_prefwidth=4.25 maxuncoupledlength=1000
FabricationTestPointUsage TestPointUsage [All] p1: valid=2 allowmultiple=FALSE
FabricationTestpoint Testpoint [All] p1: side=3 testpointundercomponent=TRUE minsize=40 maxsize=100 preferedsize=60 minholesize=0 maxholesize=40 preferedholesize=32 testpointgrid=1 allowsidetop=TRUE allowsidebottom=TRUE usegrid=TRUE gridtolerance=0.01
FanoutControl Fanout_LCC [IsLCC] p1: bgadir=Out bgaviamode=Centered fanoutstyle=Auto fanoutdirection=Alternating viagrid=1 // Fanout_LCC (Default Rule)
FanoutControl Fanout_BGA [IsBGA] p2: bgadir=Out bgaviamode=Centered fanoutstyle=Auto fanoutdirection=Alternating viagrid=1 // Fanout_BGA (Default Rule)
FanoutControl Fanout_Default [All] p4: bgadir=Out bgaviamode=Centered fanoutstyle=Auto fanoutdirection=Alternating viagrid=1 // Fanout_Default (Default Rule)
FanoutControl Fanout_Small [(CompPinCount < 5)] p5: bgadir=Out bgaviamode=Centered fanoutstyle=Auto fanoutdirection=OutThenIn viagrid=1 // Fanout_Small (Default Rule)
HoleSize [All] p1: absolutevalues=TRUE maxlimit=251 minlimit=7.87 maxpercent=80.000 minpercent=20.000
MatchedLengths LMK_LMX_DCLK [InxSignalClass('LMK_LMX_DCLK')] p1: tolerance=5 checknetsindiffpair=FALSE checkdiffpairvsdiffpair=TRUE checkxsignals=TRUE checkothers=TRUE
MatchedLengths LMK04832_FPGA [InxSignalClass('LMK04832_FPGA')] p2: tolerance=5 checknetsindiffpair=FALSE checkdiffpairvsdiffpair=TRUE checkxsignals=TRUE checkothers=TRUE
MatchedLengths FPGA_JESD [InxSignalClass('FPGA_JESD')] p3: tolerance=5 checknetsindiffpair=FALSE checkdiffpairvsdiffpair=TRUE checkxsignals=TRUE checkothers=TRUE
MatchedLengths DiffPair_MatchedLengths [InDifferentialPair ('BCLK')] p4: tolerance=1000 checknetsindiffpair=TRUE checkdiffpairvsdiffpair=FALSE checkxsignals=FALSE checkothers=FALSE
MinimumAnnularRing MinimumAnnularRing_ThermalPadVias [IsVia and InAnyComponent] p1: minimumring=5.91
MinimumAnnularRing [All] p2: minimumring=5
MinimumSolderMaskSliver MinimumSolderMaskSliver_Logo [InComponentClass('Logo') vs InComponentClass('Logo')] p1: minsoldermaskwidth=0.7
MinimumSolderMaskSliver [All] p2: minsoldermaskwidth=3.94
PlaneConnect [All] p1: planeconnectstyle=Relief reliefexpansion=10 reliefentries=4 reliefconductorwidth=10 reliefairgap=10
PolygonConnect [All] p1: connectstyle=Direct reliefconductorwidth=20 reliefentries=4 polygonreliefangle="90 Angle" airgapwidth=15
RoomDefinition TIDA-010131-E3_LMX2594R_2 [InComponentClass('TIDA-010131-E3_LMX2594R_2')] p1: confinementstyle=ConfineIn formatcopy=TRUE lockcomponents=FALSE outline -16.33,2483.66 1145.31,2483.66 1145.31,214.77 -16.33,214.77
RoomDefinition TIDA-01021_E3_LMX2594R_1 [InComponentClass('TIDA-01021_E3_LMX2594R_1')] p2: confinementstyle=ConfineIn formatcopy=TRUE lockcomponents=FALSE outline -43.75,4810.88 1141.65,4810.88 1141.65,2713.57 -43.75,2713.57
RoutingVias ThermalPadVias [IsVia and InAnyComponent] p1: holewidth=7.87 width=19.68 viastyle="Through Hole" minholewidth=7.87 minwidth=19.68 maxholewidth=12 maxwidth=24
RoutingVias [All] p2: holewidth=12 width=24 viastyle="Through Hole" minholewidth=7.87 minwidth=19.68 maxholewidth=16 maxwidth=32
SMDToCorner [All] p1: distance=30000
SilkToSilkClearance [All] p1: silktosilkclearance=5
SilkToSolderMaskClearance SilkscreenOverComponentPads [IsPad] p1: minsilkscreentomaskgap=5 clearancetoexposedcopper=TRUE
SolderMaskExpansion [All] p1: expansion=2.5
Width Width_PWR [InNetClass('PWR')] p1: maxlimit=100 minlimit=10 preferedwidth=20
Width [All] p2: maxlimit=100 minlimit=6 preferedwidth=10.5 toplayer_prefwidth=24 bottomlayer_prefwidth=13.5 minimp=50.000000 maximp=50.000000 favimp=50.000000 checkconnectedcopper=TRUE
16 further rules are at their usual default settings.

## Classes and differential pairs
differential pair class 100OHM: CLKIN0 CLKIN0* CLKIN1 CLKINN1 CLKINN1* clkinp CRCLK crclk** DCLKOUT0 DCLKOUT0* DCLKOUT0** DCLKOUT2 DCLKOUT2* DCLKOUT2** DCLKOUT12 DCLKOUT12* F_CORECLK1 F_CORECLK1* F_CORECLK2 F_CORECLK2* F_REFCLK1 F_REFCLK1* F_REFCLK2 F_REFCLK2* F_SYSREF1 F_SYSREF1* F_SYSREF2 F_SYSREF2* LMX1_REF LMX1_REF* LMX1_REF*** lmx1_sysref LMX2_REF LMX2_REF* LMX2_REF*** lmx2_sysref OSC OSCIN OSCIN* OSCOUT OSCOUT* OSCOUT** OUT SDCLKOUT1 SDCLKOUT1* SDCLKOUT1** SDCLKOUT1*** SDCLKOUT1**** SDCLKOUT3 SDCLKOUT3* SDCLKOUT3** SDCLKOUT3*** SDCLKOUT3**** SDCLKOUT5 SDCLKOUT5* SDCLKOUT5** SDCLKOUT5*** SDCLKOUT11 SDCLKOUT11* SDCLKOUT11** SDCLKOUT11*** SDCLKOUT13 SDCLKOUT13* Tmp
differential pair class USB_DIFF_90OHM: USB USB*
component class TIDA-010131-E3_LMK0482x: C3 C4 C5 C6 C7 C8 C9 C10 C11 C12 C13 C14 C15 C16 C17 C18 C19 C20 C21 C22 C176 C177 C178 C179 C184 C185 C186 C187 C188 J1 J3 J4 J7 J8 J9 J11 J13 J15 J16 L36 OSCinN OSCinP R1 R2 R3 R4 R5 R6 R7 R8 R9 R10 R11 R12 R13 R14 R15 R16 R17 R18 R19 R20 R21 R22 R23 R24 R25 R27 R28 R29 R30 R31 R32 R33 R34 R35 R36 R37 R38 R39 R40 R41 R42 R43 R44 R45 R46 R47 R48 R49 R50 R51 R52 R53 R54 R55 R56 R57 R58 R59 R60 R61 R62 R63 R64 R65 R66 R67 R70 R182 R183 R184 R190 R198 R199 R270 R282 R283 R284 R285 R286 R287 R288 R289 R290 R291 R292 R293 R297 R298 R299 R336 R337 R338 R339 R343 R344 R345 R346 R347 R356 R357 R366 R367 SYNC U1 U2 Y1
component class Header: J8 J10 J12 J14 J16 J20 J23 J33
component class "TIDA-010131-E3_LMK0482x _CLK_PWR": C1 C2 C24 C25 C26 C27 C28 C29 C30 C31 C32 C33 C34 C35 C36 C37 C38 C39 C189 C190 C191 C209 C210 C211 C212 C213 D1 D2 D3 D4 J2 J5 J21 J22 J24 J32 J33 L1 L2 L3 L4 L5 L6 L7 L8 L9 L10 R26 R68 R69 R71 R72 R73 R74 R75 R76 R77 R78 R79 R80 R191 R192 R193 R194 R195 R196 R197 R200 R201 R202 R203 R204 R208 R209 R227 R251 R252 R253 R254 R255 R256 R257 R258 R271 R272 R273 R322 R323 R324 R327 R328 R330 R333 R334 T1 U13 U14 U21
component class Label: LBL1
component class AssemblyNote: ZZ1 ZZ2 ZZ3 ZZ4
component class FiducialMark: FID1 FID2 FID3 FID4 FID5 FID6
component class TIDA-010131-E3_Hardware: FID1 FID2 FID3 FID4 FID5 FID6 LBL1 Logo1 Logo2 Logo3 Logo4 s1 S2 S3 S4 ZZ1 ZZ2 ZZ3 ZZ4
pad class MH: S1-1 S2-1 S3-1 S4-1
component class TIDA-010131-E3_LMX2594R_1: C44 C45 C46 C47 C48 C49 C50 C51 C52 C53 C54 C55 C56 C57 C58 C59 C60 C61 C62 C63 C64 C65 C66 C67 C68 C69 C70 C71 C72 C192 CE_TP1 D5 J18 J26 L11 L12 OSCinM1 OSCinP1 R81 R82 R83 R84 R85 R86 R87 R88 R89 R90 R91 R92 R93 R94 R95 R96 R97 R98 R99 R100 R101 R102 R103 R104 R105 R106 R107 R108 R109 R110 R111 R112 R113 R133 R134 R165 R213 R214 R274 R275 R276 R348 R349 R350 R351 R358 R359 R362 R363 RFoutAM1 RFoutAP1 RFoutBM1 RFoutBP1 RMPCLK1 RMPDIR1 U3 U23 Vcc_TP1 Vtune_TP1
component class TIDA-010131-E3_LMX2594R_2: C77 C78 C79 C80 C81 C82 C83 C84 C85 C86 C87 C88 C89 C90 C91 C92 C93 C94 C95 C96 C97 C98 C99 C100 C101 C102 C103 C104 C105 C193 CE_TP2 D6 J27 J28 L13 L14 OSCinM2 OSCinP2 R114 R115 R116 R117 R118 R119 R120 R121 R122 R123 R124 R125 R126 R127 R128 R129 R130 R131 R132 R135 R136 R137 R138 R139 R140 R141 R142 R143 R144 R145 R146 R168 R215 R216 R277 R278 R279 R280 R281 R300 R301 R352 R353 R354 R355 R360 R361 R364 R365 RFoutAM2 RFoutAP2 RFoutBM2 RFoutBP2 RMPCLK2 RMPDIR2 U4 U24 Vcc_TP2 Vtune_TP2
component class "TIDA-010131-E3_POWER SUPPLIES": C40 C41 C42 C43 C73 C74 C75 C123 C127 C128 C129 C131 C132 C133 C134 C135 C136 C137 C138 C139 C140 C141 C142 C143 C144 C145 C146 C147 C148 C149 C150 C151 C152 C153 C154 C155 C156 C157 C158 C159 C160 C161 C162 C163 C164 C175 C180 C181 C182 C183 C194 C195 C196 C197 C205 C206 C207 C208 D8 D9 D11 D13 D14 D15 D17 J6 J25 L18 L19 L20 L21 L22 L23 L24 L25 L26 L27 L28 L29 L30 L31 L32 L33 L34 L35 Q1 R164 R166 R167 R169 R170 R171 R174 R175 R176 R177 R179 R180 R220 R221 R222 R223 R224 R226 R228 R229 R230 R231 R232 R259 R260 R261 R294 R295 R325 R326 R329 R331 R332 R342 S5 TP1 TP2 TP4 TP5 TP6 TP7 TP8 TP9 TP10 TP11 TP12 TP13 TP14 TP15 TP16 TP20 U8 U9 U10 U11 U12 U17 U22
component class TIDA-010131-E3_USB: C23 C106 C107 C108 C109 C110 C111 C112 C113 C114 C115 C116 C117 C118 C119 C120 C121 C122 C124 C125 C126 C198 C199 D7 D10 D12 J17 J19 J20 J23 L15 L16 L17 R147 R148 R149 R150 R151 R152 R153 R154 R155 R156 R157 R158 R159 R160 R161 R162 R163 R172 R173 R178 R181 R185 R186 R187 R188 R189 R205 R206 R207 R210 R211 R212 R217 R218 R219 R225 R296 R302 R303 R304 R305 R306 R307 R308 R309 R310 R311 R312 R313 R314 R315 R335 R340 R341 U5 U6 U7 U15 U18 U19 VCCCORE Y2
component class TIDA-010131-E3_LMK00304_Buffer: C76 C130 C165 C166 C167 C168 C169 C170 C171 C172 C173 C174 C200 C201 C202 C203 C204 D16 J10 J12 J14 Q2 Q3 R233 R234 R235 R236 R237 R238 R239 R240 R241 R242 R243 R244 R245 R246 R247 R248 R249 R250 R262 R263 R264 R265 R266 R267 R268 R269 R316 R317 R318 R319 R320 R321 TP17 TP18 TP19 U16 U20
differential pair class CPW_100OHM: ADC_CLK1 ADC_CLK2 ADC_SYSREF1 ADC_SYSREF2 LMX_OSCIN1 LMX_OSCIN2
differential pair DCLKout2_LMK: +DCLKout2_LMK_P -DCLKout2_LMK_N
differential pair DCLKout0_LMK: +DCLKout0_LMK_P -DCLKout0_LMK_N
differential pair DCLKout2_LMX: +DCLKout2_LMK_P -DCLKout2_LMK_N
differential pair DCLKout0_LMX: +DCLKout0_LMK_P -DCLKout0_LMK_N
differential pair lmx2_sysref: +SDCLKout3_LMK_P -SDCLKout3_LMK_N
differential pair lmx1_sysref: +SDCLKout1_LMK_P -SDCLKout1_LMK_N
differential pair Tmp: +NetC204_1 -NetC203_2
differential pair clkinp: +CLKINN* -CLKINP*
differential pair crclk**: +CLKINP -CLKINN
differential pair LMX2_REF***: +NetR266_2 -NetR268_2
differential pair LMX1_REF***: +NetR262_2 -NetR264_2
differential pair CLKINN1: +NetC27_1 -NetC29_1
differential pair SDCLKOUT5*: +SDCLKOUT5+ -SDCLKOUT5-
differential pair USB: +DP -DM
differential pair USB*: +USB_DP -USB_DM
differential pair OSC: +OSCI -OSCO
differential pair SDCLKOUT13*: +SDCLKOUT13+ -SDCLKOUT13-
differential pair SDCLKOUT13: +SDCLKOUT13_P -SDCLKOUT13_N
differential pair SDCLKOUT11*: +SDCLKOUT11+ -SDCLKOUT11-
differential pair SDCLKOUT11: +SDCLKOUT11_P -SDCLKOUT11_N
differential pair SDCLKOUT3*: +SDCLKOUT3+ -SDCLKOUT3-
differential pair SDCLKOUT1*: +SDCLKOUT1+ -SDCLKOUT1-
differential pair OSCIN*: +OSCIN+ -OSCIN-
differential pair F_SYSREF2*: +F_SYSREF2+ -F_SYSREF2-
differential pair F_SYSREF1*: +F_SYSREF1+ -F_SYSREF1-
differential pair F_REFCLK2*: +F_REFCLK2+ -F_REFCLK2-
differential pair F_REFCLK1*: +F_REFCLK1+ -F_REFCLK1-
differential pair F_CORECLK2*: +F_CORECLK2+ -F_CORECLK2-
differential pair F_CORECLK1: +F_CORECLK1_P -F_CORECLK1_N
differential pair F_CORECLK1*: +F_CORECLK1+ -F_CORECLK1-
differential pair DCLKOUT12*: +DCLKOUT12+ -DCLKOUT12-
differential pair DCLKOUT2*: +DCLKOUT2+ -DCLKOUT2-
differential pair DCLKOUT0*: +DCLKOUT0+ -DCLKOUT0-
differential pair ADC_SYSREF2: +ADC_SYSREF2+ -ADC_SYSREF2-
differential pair ADC_SYSREF1: +ADC_SYSREF1+ -ADC_SYSREF1-
differential pair ADC_CLK2: +ADC_CLK2+ -ADC_CLK2-
differential pair CLKIN0: +CLKIN0_P -CLKIN0_N
differential pair CLKIN1: +CLKIN1_P -CLKIN1_N
differential pair DCLKOUT0: +DCLKOUT0_P -DCLKOUT0_N
differential pair DCLKOUT2: +DCLKOUT2_P -DCLKOUT2_N
differential pair DCLKOUT12: +DCLKOUT12_P -DCLKOUT12_N
differential pair F_CORECLK2: +F_CORECLK2_P -F_CORECLK2_N
differential pair F_REFCLK1: +F_REFCLK1_P -F_REFCLK1_N
differential pair F_REFCLK2: +F_REFCLK2_P -F_REFCLK2_N
differential pair F_SYSREF1: +F_SYSREF1_P -F_SYSREF1_N
differential pair F_SYSREF2: +F_SYSREF2_P -F_SYSREF2_N
differential pair OSCIN: +OSCIN_P -OSCIN_N
differential pair OSCOUT: +OSCOUT_P -OSCOUT_N
differential pair SDCLKOUT1: +SDCLKOUT1_P -SDCLKOUT1_N
differential pair SDCLKOUT5: +NetJ13_1 -NetJ15_1
differential pair SDCLKOUT5**: +SDCLKOUT5_P -SDCLKOUT5_N
differential pair SDCLKOUT11**: +NetJ1_1 -NetJ4_1
differential pair CLKIN0*: +CLKINP0 -CLKINN0
differential pair CLKINN1*: +CLKINP1 -CLKINN1
differential pair OUT: +OUT_P -OUT_N
differential pair OSCOUT*: +NetC174_1 -NetC173_1
differential pair OSCOUT**: +NetC174_2 -NetC173_2
differential pair LMX2_REF: +LMX2_REFP -LMX2_REFN
differential pair LMX1_REF: +LMX1_REFP -LMX1_REFN
differential pair LMX1_REF*: +NetR240_1 -NetR241_1
differential pair LMX2_REF*: +NetR242_1 -NetR243_1
differential pair ADC_CLK1: +ADC_CLK1+ -ADC_CLK1-
differential pair LMX_OSCIN1: +LMX_OSCIN1+ -LMX_OSCIN1-
differential pair LMX_OSCIN2: +LMX_OSCIN2+ -LMX_OSCIN2-
differential pair DCLKOUT0**: +DCLKOUT0_P* -DCLKOUT0_N*
differential pair SDCLKOUT1**: +"" -""
differential pair DCLKOUT2**: +DCLKOUT2_P* -DCLKOUT2_N*
differential pair SDCLKOUT3**: +SDCLKOUT3_P -SDCLKOUT3_N
differential pair SDCLKOUT11***: +SDCLKOUT11+* -SDCLKOUT11-*
differential pair SDCLKOUT5***: +SDCLKOUT5+* -SDCLKOUT5-*
differential pair SDCLKOUT1***: +SDCLKOUT1+* -SDCLKOUT1-*
differential pair SDCLKOUT3***: +SDCLKOUT3+* -SDCLKOUT3-*
differential pair CRCLK: +"" -""
differential pair SDCLKOUT1****: +NetR276_2 -NetR134_1
differential pair SDCLKOUT3****: +NetR301_2 -NetR300_1

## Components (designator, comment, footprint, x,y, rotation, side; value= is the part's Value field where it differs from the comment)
C1 "C0603C104J3RACTU" 0603 4054,2955 r0 top value=0.1uF
C2 "GRM155R71C104KA88D" 0402#1 4036.97,1890.65 r270 bottom value=0.1uF
C3 "C1005X7R1E104M050BB" 0402#1 2889.84,2997.2 r180 top value=0.1uF
C4 "C1005X7R1E104M050BB" 0402#1 2889.84,2943.4 r180 top value=0.1uF
C5 "C1005X7R1E104M050BB" 0402#1 2892.51,2745.88 r0 top value=0.1uF
C6 "C1005X7R1E104M050BB" 0402#1 2892.51,2696.88 r0 top value=0.1uF
C7 "GRM0335C1E470JA01D" 0201_033 3790.57,2639.78 r0 top value=47pF
C8 "0201ZD392KAT2A" 0201 3790.57,2674.78 r0 top value=3900pF
C9 "C1005X7R1E104M050BB" 0402#1 4067.07,2656.86 r0 top value=0.1uF
C10 "C1005X7R1E104M050BB" 0402#1 6093.97,2902.39 r270 bottom value=0.1uF
C11 "C0402C120J3GACAUTO" 0402#1 3991.22,2679.69 r270 top value=12pF
C12 "C1005X7R1E104M050BB" 0402#1 4067.07,2599.1 r0 top value=0.1uF
C13 "C0805C106K8PACTU" 0805_HV 3220.57,2424.78 r270 bottom value=10uF
C14 "C0603C104J3RACTU" 0603 3356.72,2447.39 r0 bottom value=0.1uF
C15 "C1005X7R1E104M050BB" 0402#1 3060.95,2274.97 r0 top value=0.1uF
C16 "C1005X7R1E104M050BB" 0402#1 3061.57,2224.97 r0 top value=0.1uF
C17 "C1005X5R1A684K050BB" 0402#1 3730.86,2260.15 r90 top value=0.68uF
C18 "C0603C330J5GACTU" 0603L 3290.72,2350.39 r270 bottom value=33pF
C19 "04025A101FAT2A" 0402#1 6043.97,2902.39 r270 bottom value=100pF
C20 "C0603C330J5GACTU" 0603L 3375.72,2359.39 r270 bottom value=33pF
C21 "C0603C330J5GACTU" 0603L 3427.72,2359.39 r270 bottom value=33pF
C22 "C1005X7R1E104M050BB" 0402#1 3992.22,2575.69 r90 top value=0.1uF
C23 "C0603C104J3RACTU" 0603 5185,1276.66 r0 top value=0.1uF
C24 "GRM033R60J104KE19D" 0201_033 3863.18,2439.88 r180 top value=0.1uF
C25 "GRM033R60J104KE19D" 0201_033 3862.97,2479.66 r180 top value=0.1uF
C26 "C1005X7S1A105K050BC" 0402#1 3305.57,2211.78 r270 bottom value=1uF
C27 "GRM033R60J104KE19D" 0201_033 3839,2337.19 r180 top value=0.1uF
C28 "C1005X7S1A105K050BC" 0402#1 3365.72,2216.39 r270 bottom value=1uF
C29 "GRM033R60J104KE19D" 0201_033 3839,2361.79 r180 top value=0.1uF
C30 "GRM033R60J104KE19D" 0201_033 3795,2376 r270 top value=0.1uF
C31 "C1005X7S1A105K050BC" 0402#1 3482.57,2224.78 r270 bottom value=1uF
C32 "C1005X7S1A105K050BC" 0402#1 3636.57,2817.29 r90 bottom value=1uF
C33 "C1005X7S1A105K050BC" 0402#1 3285.69,2791.51 r90 bottom value=1uF
C34 "C1005X7S1A105K050BC" 0402#1 3656.57,2409.78 r180 bottom value=1uF
C35 "GRM155R71C104KA88D" 0402#1 3657.57,2359.78 r180 bottom value=0.1uF
C36 "GRM155R71E103KA01D" 0402#1 3350.72,2505.39 r0 bottom value=0.01uF
C37 "C1005X7S1A105K050BC" 0402#1 3855.57,2265.78 r0 bottom value=1uF
C38 "GRM155R71C104KA88D" 0402#1 3855.57,2314.78 r0 bottom value=0.1uF
C39 "GRM155R71E103KA01D" 0402#1 3855.57,2364.78 r0 bottom value=0.01uF
C40 "GRM155R71C104KA88D" 0402#1 4981.97,4436.66 r180 top value=0.1uF
C41 "GRM155R71C104KA88D" 0402#1 5133.97,4255.66 r270 top value=0.1uF
C42 "885012208019" 1206_190 5389.03,4005.03 r90 top value=22uF
C43 "885012208019" 1206_190 5481.03,4005.03 r90 top value=22uF
C44 "520L103KT16T" 0402_065 369.54,3061.91 r0 top value=0.01uF
C45 "520L103KT16T" 0402_065 731.7,3310.06 r0 top value=0.01uF
C46 "C1608X7R1C105K080AC" 0603 1313.8,3229.85 r180 bottom value=1uF
C47 "C1608X7R1C105K080AC" 0603L 1186.7,3417.35 r225 top value=1uF
C48 "520L103KT16T" 0402_065 369.54,3561.91 r0 top value=0.01uF
C49 "C1608X7R1C105K080AC" 0603L 1011.7,3368.25 r270 bottom value=1uF
C50 "0603YC104JAT2A" 0603L 904.5,3321.75 r135 bottom value=0.1uF
C51 "0603YC104JAT2A" 0603 901.1,2717.64 r180 top value=0.1uF
C52 "C0805C106K8PACTU" 0805 904.1,2795.44 r180 top value=10uF
C53 "C0805C106K8PACTU" 0805 1589.7,3856.55 r180 top value=10uF
C54 "0603YC104JAT2A" 0603 1586.7,3932.35 r180 top value=0.1uF
C55 "C1608X7R1C105K080AC" 0603 735.6,3107.97 r90 top value=1uF
C56 "C1608X7R1C105K080AC" 0603 1103.4,2977.35 r90 top value=1uF
C57 "520L103KT16T" 0402_065 368.96,4562.93 r0 top value=0.01uF
C58 "GRM1885C1H182JA01D" 0603 994.1,2977.35 r90 top value=1800pF
C59 "GRM1885C2A301JA01D" 0603 1406.7,3642.35 r45 top value=300pF
C60 "GRM188R71H563KA93D" 0603 1266.7,3592.35 r45 top value=0.056uF
C61 "520L103KT16T" 0402_065 950.28,3530.75 r270 top value=0.01uF
C62 "GRM1885C1H152JA01J" 0603 1221.58,3499.54 r315 top value=1500pF
C63 "C1608X7R1C105K080AC" 0603 1126.2,3360.69 r0 bottom value=1uF
C64 "520L103KT16T" 0402_065 369.15,4060.24 r0 top value=0.01uF
C65 "C1608X5R1A106M080AC" 0603 1048.5,2977.35 r270 top value=10uF
C66 "C1608X7R1C105K080AC" 0603 1157.8,3076.85 r180 top value=1uF
C67 "C1608X5R1A106M080AC" 0603 883,2977.35 r270 top value=10uF
C68 "C1608X5R1A106M080AC" 0603 1261.7,3207.35 r0 top value=10uF
C69 "C1608X5R1A106M080AC" 0603 799.7,3107.56 r90 top value=10uF
C70 "C1608X5R1A106M080AC" 0603 939.4,2977.35 r90 top value=10uF
C71 "0603YC104JAT2A" 0603L 1286.3,3285.55 r180 top value=0.1uF
C72 "0603YC104JAT2A" 0603L 1284.6,3340.72 r180 top value=0.1uF
C73 "885012208019" 1206_190 5571.03,4005.03 r90 top value=22uF
C74 "GRM155R71E103KA01D" 0402#1 4829,4181 r180 top value=0.01uF
C75 "GRM188R71E103KA01D" 0603 4719.97,4270.66 r270 top value=0.01uF
C76 "GRM188R61A106ME69D" 0603 2469.82,2229.41 r180 top value=10uF
C77 "520L103KT16T" 0402_065 368.78,664.01 r0 top value=0.01uF
C78 "520L103KT16T" 0402_065 730.95,912.16 r0 top value=0.01uF
C79 "C1608X7R1C105K080AC" 0603 1313.05,831.94 r180 bottom value=1uF
C80 "C1608X7R1C105K080AC" 0603L 1185.95,1019.44 r225 top value=1uF
C81 "520L103KT16T" 0402_065 368.78,1164.01 r0 top value=0.01uF
C82 "C1608X7R1C105K080AC" 0603L 1010.95,970.34 r270 bottom value=1uF
C83 "0603YC104JAT2A" 0603L 903.75,923.84 r135 bottom value=0.1uF
C84 "0603YC104JAT2A" 0603 903.94,316.88 r180 top value=0.1uF
C85 "C0805C106K8PACTU" 0805 906.94,394.68 r180 top value=10uF
C86 "C0805C106K8PACTU" 0805 1588.95,1458.64 r180 top value=10uF
C87 "0603YC104JAT2A" 0603 1585.95,1534.44 r180 top value=0.1uF
C88 "C1608X7R1C105K080AC" 0603 734.84,709.46 r90 top value=1uF
C89 "C1608X7R1C105K080AC" 0603 1102.65,579.44 r90 top value=1uF
C90 "520L103KT16T" 0402_065 371.13,2165.1 r0 top value=0.01uF
C91 "GRM1885C1H182JA01D" 0603 993.35,579.44 r90 top value=1800pF
C92 "GRM1885C2A301JA01D" 0603 1405.95,1244.44 r45 top value=300pF
C93 "GRM188R71H563KA93D" 0603 1265.95,1194.44 r45 top value=0.056uF
C94 "520L103KT16T" 0402_065 949.71,1128.27 r270 top value=0.01uF
C95 "GRM1885C1H152JA01J" 0603 1221.38,1102.2 r315 top value=1500pF
C96 "C1608X7R1C105K080AC" 0603 1125.44,962.79 r0 bottom value=1uF
C97 "520L103KT16T" 0402_065 371.13,1664.99 r0 top value=0.01uF
C98 "C1608X5R1A106M080AC" 0603 1047.75,579.44 r270 top value=10uF
C99 "C1608X7R1C105K080AC" 0603 1157.05,678.94 r180 top value=1uF
C100 "C1608X5R1A106M080AC" 0603 882.25,579.44 r270 top value=10uF
C101 "C1608X5R1A106M080AC" 0603 1260.95,809.44 r0 top value=10uF
C102 "C1608X5R1A106M080AC" 0603 798.95,709.66 r90 top value=10uF
C103 "C1608X5R1A106M080AC" 0603 938.65,579.44 r90 top value=10uF
C104 "0603YC104JAT2A" 0603L 1285.55,887.64 r180 top value=0.1uF
C105 "0603YC104JAT2A" 0603L 1283.85,942.82 r180 top value=0.1uF
C106 "GRM188R61A106ME69D" 0603 5583.62,509.86 r90 bottom value=10uF
C107 "GRM188R61A106ME69D" 0603 5489.2,639.02 r90 bottom value=10uF
C108 "C0603C104J3RACTU" 0603 5324.2,638.02 r270 bottom value=0.1uF
C109 "C0603C104J3RACTU" 0603 5260.78,411.44 r90 bottom value=0.1uF
C110 "C0603C104J3RACTU" 0603 5583.2,638.02 r90 bottom value=0.1uF
C111 "C0603C104J3RACTU" 0603 5357.2,792.02 r180 bottom value=0.1uF
C112 "GRM188R61A106ME69D" 0603 5343.2,787.02 r90 top value=10uF
C113 "C0603C104J3RACTU" 0603 5736.2,392.02 r180 top value=0.1uF
C114 "C0603C104J3RACTU" 0603 5280.2,787.02 r90 top value=0.1uF
C115 "C0603C104J3RACTU" 0603 5736.2,311.02 r180 top value=0.1uF
C116 "GRM155R71E103KA01D" 0402#1 5488.2,359.4 r90 bottom value=0.01uF
C117 "C0603C104J3RACTU" 0603 5520.2,510.02 r90 bottom value=0.1uF
C118 "C1608X7R1C105K080AC" 0603 6340.5,678 r90 top value=1uF
C119 "GRM32ER61A107ME20L" 1210_270 6166.26,422.31 r270 top value=100uF
C120 "C0603C104J3RACTU" 0603 6309.26,481.4 r180 top value=0.1uF
C121 "C1608X7R1C105K080AC" 0603 6235.5,823 r180 top value=1uF
C122 "GRM155R71E103KA01D" 0402#1 6473,980 r270 top value=0.01uF
C123 "GRM188R61A106ME69D" 0603 5376,3654 r180 top value=10uF
C124 "C0603C104J3RACTU" 0603 5936.2,657.02 r270 top value=0.1uF
C125 "GRM1885C2A270JA01D" 0603 5642.51,925.93 r180 top value=27pF
C126 "GRM1885C2A270JA01D" 0603 5512.51,925.93 r180 top value=27pF
C127 "08053D105KAT2A" 0805_HV 5617.18,4440.01 r90 top value=1uF
C128 "08053D105KAT2A" 0805_HV 5527.18,4440.01 r90 top value=1uF
C129 "GRM188R61A106ME69D" 0603 4983.97,4493.66 r180 top value=10uF
C130 "C1005X7S1A105K050BC" 0402#1 2461.82,2287.91 r180 top value=1uF
C131 "08053D105KAT2A" 0805_HV 6007.18,4449.01 r90 top value=1uF
C132 "06031C102MAT2A" 0603 6152.18,4230.01 r0 top value=1000pF
C133 "06031C102MAT2A" 0603 5982.18,4265.01 r270 top value=1000pF
C134 "GRM188R61A106ME69D" 0603 6524.14,2211.25 r0 top value=10uF
C135 "GRM155R71C104KA88D" 0402#1 6174.43,2244.25 r90 top value=0.1uF
C136 "C1005X7S1A105K050BC" 0402#1 6124.43,2246.24 r90 top value=1uF
C137 "C3225X5R1A476M250AC" 1210_280 6034.43,2239.25 r90 top value=47uF
C138 "GRM188R61A106ME69D" 0603 6501,3787.5 r0 top value=10uF
C139 "GRM155R71C104KA88D" 0402#1 6153,3814.5 r90 top value=0.1uF
C140 "C1005X7S1A105K050BC" 0402#1 6103,3814.5 r90 top value=1uF
C141 "C3225X5R1A476M250AC" 1210_280 6013,3809.5 r90 top value=47uF
C142 "C2012X5R1A336M125AC" 0805_HV 5789.43,1938.25 r90 top value=33uF
C143 "GRM188R61A106ME69D" 0603 5709.43,1938.25 r270 top value=10uF
C144 "GRM155R71C104KA88D" 0402#1 5652.62,1934.47 r90 top value=0.1uF
C145 "GRM155R71E103KA01D" 0402#1 5602.62,1934.47 r90 top value=0.01uF
C146 "C2012X5R1A336M125AC" 0805_HV 5868.85,3539.98 r90 top value=33uF
C147 "GRM188R61A106ME69D" 0603 5788.85,3539.98 r270 top value=10uF
C148 "GRM155R71C104KA88D" 0402#1 5732.04,3536.2 r90 top value=0.1uF
C149 "GRM155R71E103KA01D" 0402#1 5682.04,3536.2 r90 top value=0.01uF
C150 "C1005X7S1A105K050BC" 0402#1 6394.43,2159.25 r180 bottom value=1uF
C151 "C1005X7S1A105K050BC" 0402#1 6375,3750 r180 bottom value=1uF
C152 "GRM188R61A106ME69D" 0603 5635,2140.5 r90 top value=10uF
C153 "GRM155R71C104KA88D" 0402#1 5579,2136.5 r270 top value=0.1uF
C154 "GRM188R61A106ME69D" 0603 2930,4755.26 r0 top value=10uF
C155 "GRM155R71C104KA88D" 0402#1 2674,4846.26 r90 top value=0.1uF
C156 "C1005X7S1A105K050BC" 0402#1 2624,4846.26 r90 top value=1uF
C157 "C3225X5R1A476M250AC" 1210_280 2523,4801.26 r90 top value=47uF
C158 "C2012X5R1A336M125AC" 0805_HV 2197.29,4692.47 r90 top value=33uF
C159 "GRM188R61A106ME69D" 0603 2117.29,4692.47 r270 top value=10uF
C160 "GRM155R71C104KA88D" 0402#1 2060.48,4688.69 r90 top value=0.1uF
C161 "C1005X7S1A105K050BC" 0402#1 2010.48,4688.69 r90 top value=1uF
C162 "GRM155R71C104KA88D" 0402#2 9541.07,5797.71 r180 bottom value=0.1uF
C163 "GRM188R61A106ME69D" 0603 2205.08,4877.87 r90 top value=10uF
C164 "GRM155R71C104KA88D" 0402#1 2031.08,4880.87 r270 top value=0.1uF
C165 "GRM155R71C104KA88D" 0402#1 2157.32,2154.91 r90 top value=0.1uF
C166 "GRM155R71E103KA01D" 0402#1 2194.82,2396.91 r0 bottom value=0.01uF
C167 "GRM155R71E103KA01D" 0402#1 2188.2,2262.28 r0 bottom value=0.01uF
C168 "GRM155R71E103KA01D" 0402#1 2193.82,2336.91 r0 bottom value=0.01uF
C169 "GRM155R71E103KA01D" 0402#1 2270.82,2411.91 r90 bottom value=0.01uF
C170 "GRM155R71E103KA01D" 0402#1 2327.82,2336.91 r180 bottom value=0.01uF
C171 "GRM155R71E103KA01D" 0402#1 2355.09,2416.29 r90 bottom value=0.01uF
C172 "GRM155R71E103KA01D" 0402#1 2194.82,2441.41 r180 bottom value=0.01uF
C173 "C1005X7R1E104M050BB" 0402#1 2275.82,2156.91 r90 top value=0.1uF
C174 "C1005X7R1E104M050BB" 0402#1 2323.82,2156.91 r90 top value=0.1uF
C175 "GRM155R71C104KA88D" 0402#1 4817,4239 r180 bottom value=0.1uF
C176 "GRM155R71E222KA01D" 0402#1 5990.97,2902.39 r270 bottom value=2200pF
C177 "GRM1555C1H100JA01D" 0402#1 5938.97,2902.77 r270 bottom value=10pF
C178 "C1005X7R1E104M050BB" 0402#1 6070.97,3133.39 r0 top value=0.1uF
C179 "C1005X7R1E104M050BB" 0402#1 5453.07,3182 r90 top value=0.1uF
C180 "GRM188R61A106ME69D" 0603 2930,4637.5 r180 top value=10uF
C181 "GRM155R71C104KA88D" 0402#1 2930,4693.5 r180 top value=0.1uF
C182 "GRM188R61A106ME69D" 0603 2142.08,4877.87 r90 top value=10uF
C183 "C1005X7S1A105K050BC" 0402#1 2082.08,4881.87 r270 top value=1uF
C184 "C1005X7R1E104M050BB" 0402#1 3353.41,2637.93 r0 bottom value=0.1uF
C185 "C1005X7R1E104M050BB" 0402#1 3207.9,2685.06 r0 bottom value=0.1uF
C186 "C1005X7R1E104M050BB" 0402#1 3681.58,2260.15 r90 top value=0.1uF
C187 "C1005X5R0J475M050BC" 0402#1 5293.97,2656.66 r180 bottom value=4.7uF
C188 "GRM155R71E103KA01D" 0402#1 5293.97,2706.66 r180 bottom value=0.01uF
C189 "C1005X7R1E104M050BB" 0402#1 3873.97,2576.66 r90 bottom value=0.1uF
C190 "C1005X7R1E104M050BB" 0402#1 3796.97,2548.66 r180 bottom value=0.1uF
C191 "C1005X7R1E104M050BB" 0402#1 3797.97,2604.66 r180 bottom value=0.1uF
C192 "0603YC104JAT2A" 0603 1800,2872 r270 bottom value=0.1uF
C193 "0603YC104JAT2A" 0603 1800,473 r270 bottom value=0.1uF
C194 "GRM188R61A106ME69D" 0603 5376,3719 r180 top value=10uF
C195 "GRM188R61A106ME69D" 0603 5376,3586 r180 top value=10uF
C196 "C2012X5R1A336M125AC" 0805_HV 5711,2135 r270 top value=33uF
C197 "GRM155R71E103KA01D" 0402#1 5527,2136 r270 top value=0.01uF
C198 "C0603C104J3RACTU" 0603 5170,1632.93 r0 top value=0.1uF
C199 "C0603C104J3RACTU" 0603 4281,361 r0 top value=0.1uF
C200 "GRM1555C1H101JA01D" 0402#1 3307.51,417.86 r90 top value=100pF
C201 "293D106X0010B2TE3" 3528-21 3214.51,457.86 r90 top value=10uF
C202 "C1005X7R1E104M050BB" 0402#1 3357.51,416.86 r90 top value=0.1uF
C203 "GRM1555C1H101JA01D" 0402#1 3326,299 r90 top value=100pF
C204 "GRM1555C1H101JA01D" 0402#1 3368,299 r90 top value=100pF
C205 "GRM188R61C106MAALD" 0603 5336.99,2222.8 r180 top value=10uF
C206 "GRM188R61C106MAALD" 0603 5200.99,2179.8 r90 top value=10uF
C207 "GRM188R71C103KA01D" 0603 5105,2133 r90 top value=0.01uF
C208 "CL10B104KO8NNNC" 0603 5353.27,2139.48 r90 bottom value=0.1uF
C209 "C1005X7R1E104M050BB" 0402#1 4264,2335 r135 top value=0.1uF
C210 "C0603C104J3RACTU" 0603 4326,2110 r135 top value=0.1uF
C211 "C1005X7R1E104M050BB" 0402#1 4094.8,2208.8 r225 bottom value=0.1uF
C212 "C1005X7R1E104M050BB" 0402#1 4186.3,2114.3 r225 bottom value=0.1uF
C213 "C1005X7R1E104M050BB" 0402#1 4142.3,2158.3 r225 bottom value=0.1uF
CE_TP1 "5007" Keystone5007 1321.7,2902.35 r180 top value=White
CE_TP2 "5007" Keystone5007 1320.95,504.44 r180 top value=White
D1 "LTST-C191TGKT" LTST-C191_Green 4028,2828 r0 top value=Green
D2 "LTST-C191TGKT" LTST-C191_Green 4028,2892 r0 top value=Green
D3 "LTST-C191TGKT" LTST-C191_Green 3935.19,2082.4 r90 top value=Green
D4 "LTST-C191TGKT" LTST-C191_Green 4027.87,2763.58 r0 top value=Green
D5 "LTST-C191TGKT" LTST-C191_Green 581.53,3651.67 r135 top value=Green
D6 "LTST-C191TGKT" LTST-C191_Green 580.77,1253.76 r135 top value=Green
D7 "PGB1010603MR" PGB1_0603 6394,1154 r270 top value=24V
D8 "SMBJ15CA" SMB-Bi 6161.66,4479.31 r270 top value=15V
D9 "MBR130T1G" SOD-123 5712.18,4465.01 r90 top value=30V
D10 "LTST-C191TGKT" LTST-C191_Green 5704.2,157.02 r90 top value=Green
D11 "LTST-C191TGKT" LTST-C191_Green 5184.3,3630.34 r270 top value=Green
D12 "PGB1010603MR" PGB1_0603 6395,1001 r90 top value=24V
D13 "LTST-C191TGKT" LTST-C191_Green 5615.85,3514.98 r90 top value=Green
D14 "LTST-C191TGKT" LTST-C191_Green 6159.36,2026.48 r270 top value=Green
D15 "LTST-C191TGKT" LTST-C191_Green 2589.5,4531.61 r270 top value=Green
D16 "LTST-C190GKT" LED_LTST-C190 3722.51,186.76 r270 top value=Green
D17 "LTST-C191TGKT" LTST-C191_Green 5186,2304 r0 top value=Green
FID1 "Fiducial" Fiducial10-20 6149,164 r90 top
FID2 "Fiducial" Fiducial10-20 6342,4921 r90 top
FID3 "Fiducial" Fiducial10-20 439,58 r0 top
FID4 "Fiducial" Fiducial10-20 439,58 r180 bottom
FID5 "Fiducial" Fiducial10-20 6149,164 r180 bottom
FID6 "Fiducial" Fiducial10-20 6342,4921 r180 bottom
J1 "142-0701-201" JOHNSON_142-0701-20X 3383.5,3975 r180 top
J2 "QSH-030-01-L-D-A" Samtec_QSH-030-01-X-D-A#1 4075.52,1073.03 r0 top
J3 "142-0701-201" JOHNSON_142-0701-20X 2478.71,3975 r270 top
J4 "142-0701-201" JOHNSON_142-0701-20X 3003.5,3975 r90 top
J5 "QSH-030-01-L-D-A" Samtec_QSH-030-01-X-D-A#2 4075.52,4044.37 r0 top
J6 "142-0701-201" Johnson_142-0701-20x 4889,3419 r0 top
J7 "142-0701-201" JOHNSON_142-0701-20X 2478.71,3595 r180 top
J8 "TSW-102-07-G-S" TSW-102-07-G-S 5595,2880 r0 top
J9 "142-0701-201" JOHNSON_142-0701-20X 2472.72,3158.59 r0 top
J10 "800-10-004-10-001000" Mill-Max_800-10-004-10-001000 2627.47,1750.77 r270 top
J11 "142-0701-201" JOHNSON_142-0701-20X 2472.72,2778.59 r0 top
J12 "800-10-004-10-001000" Mill-Max_800-10-004-10-001000 2727.47,1750.77 r270 top
J13 "142-0701-201" JOHNSON_142-0701-20X 2961.68,1062.23 r180 top
J14 "800-10-004-10-001000" Mill-Max_800-10-004-10-001000 2527.47,1750.77 r270 top
J15 "142-0701-201" JOHNSON_142-0701-20X 3345.68,1062.23 r180 top
J16 "TSW-102-07-G-S" TSW-102-07-G-S 5230.98,2573.66 r0 top
J17 "651305142821" 651305142821 6665,1092 r90 top
J18 "" Molex_0853050232 525,2649.92 r0 top
J19 "52601-S10-8LF" FCI_52601-S10-8LF 6306,1581.5 r270 top locked
J20 "TSW-104-07-G-D" TSW-104-07-G-D 5734.63,1456 r90 top locked
J21 "142-0701-201" JOHNSON_142-0701-20X 4611.35,2271.2 r270 top
J22 "32K101-400L5" Rosenberger_32K101-400L5 4678.42,1751 r225 top
J23 "0022284033" Molex_0022284033 5422,70 r0 top
J24 "142-0701-201" Johnson_142-0701-20x 2814,644 r270 top
J25 "RAPC722X" CONN_RAPC722X 6890.18,4395.46 r0 top
J26 "" Molex_0853050232 1406,2586 r0 top
J27 "" Molex_0853050232 525,252.41 r0 top
J28 "" Molex_0853050232 1405.24,188.1 r0 top
J32 "142-0701-201" JOHNSON_142-0701-20X 4611.35,2648.2 r90 top
J33 "TSW-102-07-G-S" TSW-102-07-G-S 4413.72,3006.39 r90 top
L1 "BLM18AG121SN1D" 0603 3305.57,2213.56 r90 top value="120 ohm"
L2 "BLM18AG121SN1D" 0603 3421.72,2212.39 r90 bottom value="120 ohm"
L3 "BLM18AG121SN1D" 0603 3541.57,2214.78 r90 bottom value="120 ohm"
L4 "BLM18AG121SN1D" 0603 3577.57,2830.78 r270 bottom value="120 ohm"
L5 "BLM18AG121SN1D" 0603 3284.69,2791.51 r270 top value="120 ohm"
L6 "BLM18AG121SN1D" 0603 3833.97,2453.63 r90 bottom value="120 ohm"
L7 "BLM18AG121SN1D" 0603 3686.57,2242.78 r90 bottom value="120 ohm"
L8 "BLM18AG121SN1D" 0603 3865.57,2206.78 r180 bottom value="120 ohm"
L9 "BLM18AG121SN1D" 0603 3681.57,2498.78 r90 bottom value="120 ohm"
L10 "BLM18AG121SN1D" 0603 3681.05,2626.88 r270 bottom value="120 ohm"
L11 "LQG15HS18NJ02D" IND_LQG15H 733.6,3305.97 r0 bottom value=18nH
L12 "LQG15HS18NJ02D" IND_LQG15H 950.28,3530.75 r270 bottom value=18nH
L13 "LQG15HS18NJ02D" IND_LQG15H 732.85,908.07 r0 bottom value=18nH
L14 "LQG15HS18NJ02D" IND_LQG15H 949.03,1131.93 r270 bottom value=18nH
L15 "BLM31PG121SN1L" 1206 5528.2,792.02 r180 bottom value="120 ohm"
L16 "BLM31PG121SN1L" 1206 5194.2,812.02 r270 top value="120 ohm"
L17 "BLM18SG260TN1D" 0603 6308.8,547.85 r180 top value="26 ohm"
L18 "BLM31PG121SN1L" 1206 5954.43,1861.25 r180 top value="120 ohm"
L19 "BLM31PG121SN1L" 1206 6113,3558.41 r270 top value="120 ohm"
L20 "BLM31PG121SN1L" 1206 5954.43,1965.94 r180 top value="120 ohm"
L21 "BLM31PG121SN1L" 1206 6008,3558.41 r270 top value="120 ohm"
L22 "BLM31PG121SN1L" 1206 5864.43,2279.25 r180 top value="120 ohm"
L23 "BLM31PG121SN1L" 1206 5864.43,2174.25 r180 top value="120 ohm"
L24 "BLM31PG121SN1L" 1206 2350.29,4631.47 r180 top value="120 ohm"
L25 "BLM31PG121SN1L" 1206 2350.29,4736.16 r180 top value="120 ohm"
L26 "BLM31PG121SN1L" 1206 2352.29,4953.47 r180 top value="120 ohm"
L27 "BLM31PG121SN1L" 1206 2352.29,4848.47 r180 top value="120 ohm"
L28 "BLM31PG121SN1L" 1206 6407.43,2310.63 r180 top value="120 ohm"
L29 "BLM31PG121SN1L" 1206 6385,3883.5 r180 top value="120 ohm"
L30 "BLM31PG121SN1L" 1206 6605.43,2309.63 r180 top value="120 ohm"
L31 "BLM31PG121SN1L" 1206 6583,3883.5 r180 top value="120 ohm"
L32 "BLM31PG121SN1L" 1206 2859,4908.26 r90 top value="120 ohm"
L33 "BLM31PG121SN1L" 1206 2963,4908.26 r270 top value="120 ohm"
L34 "BLM31PG121SN1L" 1206 5112.97,4558.75 r90 top value="120 ohm"
L35 "XAL7030-152MEB" XAL7030 5176.97,4030.66 r270 top value=1.5uH
L36 "BLM18SG121TN1D" 0603 5837.97,2879.39 r180 bottom value="120 ohm"
LBL1 "Size: 0.65\" x 0.20 \"" Label_650x200 3672.5,4928.44 r0 top
Logo1 "ESD Susceptible" ESD_Overlay_SMALL 6742.03,4096.12 r0 top
Logo2 "Pb-Free Symbol" Pb-Free_Overlay_Small 4161.13,4895.27 r0 top
Logo3 "FCC disclaimer" FCC_disclaimer 3956.85,5445 r180 top
Logo4 "WEEE logo" WEEE_Minimum 3685.63,4481.13 r0 top
OSCinM1 "142-0701-201" JOHNSON_142-0701-20X 2015.2,3575.35 r180 top
OSCinM2 "142-0701-201" JOHNSON_142-0701-20X 2014.45,1177.44 r180 top
OSCinN "142-0701-851" EMERSON_142-0701-851 6885.89,3205.51 r270 top locked
OSCinP "142-0701-851" EMERSON_142-0701-851 6885.89,2660.51 r270 top locked
OSCinP1 "142-0701-201" JOHNSON_142-0701-20X 2014.7,3053.15 r180 top
OSCinP2 "142-0701-201" JOHNSON_142-0701-20X 2014.45,656.94 r180 top
Q1 "CSD15571Q2" DQK0006C 5901.41,4501.61 r270 top value=20V
Q2 "BSR17A" SOT-23 1166.1,384.76 r90 top value="40 V"
Q3 "BSR17A" SOT-23 1113,2782 r180 top value="40 V"
R1 "CRCW04020000Z0ED" 0402#1 3248.37,3076.4 r0 bottom value=0
R2 "CRCW04020000Z0ED" 0402#1 3102.02,1960.89 r180 bottom value=0
R3 "CRCW04020000Z0ED" 0402#1 3221.17,3156.4 r270 top value=0
R4 "CRCW04020000Z0ED" 0402#1 3389.19,3156.4 r90 top value=0
R5 "ERJ-2RKF1000X" 0402#1 3052.99,3217.4 r270 top value=100
R6 "CRCW04020000Z0ED" 0402#1 3167.37,3156.4 r270 top value=0
R7 "CRCW04020000Z0ED" 0402#1 3442.99,3156.05 r90 top value=0
R8 "ERJ-2RKF1000X" 0402#1 2998.72,3217.39 r270 top value=100
R9 "CRCW04020000Z0ED" 0402#1 3141.37,3076.4 r180 bottom value=0
R10 "CRCW04020000Z0ED" 0402#1 3208.92,1960.89 r0 bottom value=0
R11 "CRCW0402220RJNED" 0402#1 3141.37,3076.4 r0 top value=220
R12 "CRCW0402220RJNED" 0402#1 3248.37,3076.4 r180 top value=220
R13 "CRCW0402200RFKED" 0402#1 2973.19,3137.4 r0 top value=200
R14 "CRCW0402200RFKED" 0402#1 3079.19,3137.4 r180 top value=200
R15 "CRCW0402240RJNED" 0402#1 3363.19,3076.05 r0 top value=240
R16 "CRCW0402240RJNED" 0402#1 3468.19,3076.05 r180 top value=240
R17 "CRCW0402240RJNED" 0402#1 3552.57,2969.4 r0 top value=240
R18 "CRCW0402240RJNED" 0402#1 3659.57,2969.4 r180 top value=240
R19 "CRCW04020000Z0ED" 0402#1 3791.98,3049.15 r90 top value=0
R20 "CRCW04020000Z0ED" 0402#1 3845.78,3049.15 r90 top value=0
R21 "CRCW0402120RJNED" 0402#1 2969.84,2917.4 r90 top value=120
R22 "CRCW0402120RJNED" 0402#1 2970.84,3023.4 r270 top value=120
R23 "CRCW0402240RJNED" 0402#1 3765.98,2969.15 r0 top value=240
R24 "CRCW0402240RJNED" 0402#1 3870.98,2969.15 r180 top value=240
R25 "CRCW04020000Z0ED" 0402#1 3061.16,2583.78 r0 top value=0
R26 "CRCW020149R9FKED" 0201 3963,2323.99 r90 top value=49.9
R27 "CRCW04020000Z0ED" 0402#1 3060.78,2533.78 r0 top value=0
R28 "RC0201FR-07620RL" 0201 3840.57,2659.78 r90 top value=620
R29 "CRCW0402120RJNED" 0402#1 3107.84,2493.04 r180 top value=120
R30 "CRCW0402120RJNED" 0402#1 3109.22,2633.66 r180 top value=120
R31 "CRCW0402120RJNED" 0402#1 2970.51,2669.26 r90 top value=120
R32 "CRCW0402120RJNED" 0402#1 2970.51,2772.88 r270 top value=120
R33 "CRCW0402100RFKED" 0402#1 5452.97,3070.66 r270 top value=100
R34 "CRCW040249R9FKED" 0402#1 4998.07,2972.6 r270 top value=49.9
R35 "ERJ-2RKF1002X" 0402#1 3353.97,2686.66 r180 bottom value=10.0k
R36 "CRCW040218R0JNED" 0402#1 5476.69,3205.62 r180 top value=18
R37 "CRCW04020000Z0ED" 0402#1 6366.79,3205.59 r0 top value=0
R38 "CRCW040218R0JNED" 0402#1 5476.69,2658.6 r180 top value=18
R39 "CRCW04020000Z0ED" 0402#1 6366.77,2658.59 r0 top value=0
R40 "CRCW040249R9FKED" 0402#1 4998.07,2867.6 r90 top value=49.9
R41 "CRCW04020000Z0ED" 0402#1 2891.57,2445.18 r0 top value=0
R42 "CRCW04020000Z0ED" 0402#1 2891.57,2395.18 r0 top value=0
R43 "CRCW040212K0JNED" 0402#1 5222.07,3052.6 r0 bottom value=12k
R44 "CRCW040212K0JNED" 0402#1 5173.45,2703.98 r180 bottom value=12k
R45 "CRCW04020000Z0ED" 0402#1 6339.55,3177.27 r90 top value=0
R46 "CRCW04020000Z0ED" 0402#1 6339.55,2687.65 r270 top value=0
R47 "CRCW0402120RJNED" 0402#1 3140.57,2197.97 r90 top value=120
R48 "CRCW0402120RJNED" 0402#1 3140.57,2301.97 r270 top value=120
R49 "CRCW0402120RJNED" 0402#1 2891.97,2345.66 r0 top value=120
R50 "CRCW0402120RJNED" 0402#1 2891.97,2494.66 r0 top value=120
R51 "CRCW040212K0JNED" 0402#1 5052.07,2862.6 r90 bottom value=12k
R52 "RC0201FR-0739KL" 0201 3794.97,2236.66 r180 top value=39.0k
R53 "CRCW060351R0JNEA" 0603L 3809.19,2090.4 r90 top value=51
R54 "CRCW04020000Z0ED" 0402#1 3128,1880.84 r90 top value=0
R55 "CRCW04020000Z0ED" 0402#1 3791.84,1880.08 r270 top value=0
R56 "CRCW04020000Z0ED" 0402#1 3181.8,1880.84 r90 top value=0
R57 "CRCW04020000Z0ED" 0402#1 3738.04,1880.08 r270 top value=0
R58 "CRCW0402220RJNED" 0402#1 3209,1960.84 r180 top value=220
R59 "CRCW0402220RJNED" 0402#1 3102,1960.84 r0 top value=220
R60 "CRCW0402240RJNED" 0402#1 3817.04,1960.08 r180 top value=240
R61 "CRCW0402240RJNED" 0402#1 3712.04,1960.08 r0 top value=240
R62 "CRCW04020000Z0ED" 0402#1 3349.82,1880.84 r90 top value=0
R63 "CRCW04020000Z0ED" 0402#1 3403.62,1881.18 r90 top value=0
R64 "CRCW0402240RJNED" 0402#1 3428.82,1961.18 r180 top value=240
R65 "CRCW0402240RJNED" 0402#1 3323.82,1961.18 r0 top value=240
R66 "CRCW0402240RJNED" 0402#1 3620.2,2067.84 r180 top value=240
R67 "CRCW0402240RJNED" 0402#1 3513.2,2067.84 r0 top value=240
R68 "ERJ-1GN0R00C" 0201 3917.97,2439.66 r180 top value=0
R69 "RC0201JR-0751RL" 0201 3962.97,2426.66 r90 top value=51
R70 "CRCW04020000Z0ED" 0402#1 3578.57,3049.4 r90 top value=0
R71 "CRCW06030000Z0EA" 0603 4418.83,2006.47 r90 bottom value=0
R72 "CRCW020149R9FKED" 0201 3881,2323.99 r270 top value=49.9
R73 "CRCW04020000Z0ED" 0402#1 4515,1917 r135 top value=0
R74 "RC0201FR-07100RL" 0201 3989,2349.5 r270 top value=100
R75 "CRCW0402294RFKED" 0402#1 4586,1879 r225 top value=294
R76 "CRCW0402294RFKED" 0402#1 4478,1987 r225 top value=294
R77 "CRCW0603750RFKEA" 0603 3908.03,2832.95 r0 top value=750
R78 "CRCW0603750RFKEA" 0603 3907.99,2898.78 r0 top value=750
R79 "CRCW0603750RFKEA" 0603 3867.19,2086.4 r270 top value=750
R80 "CRCW0603750RFKEA" 0603 3907.87,2763.58 r0 top value=750
R81 "CRCW04020000Z0ED" 0402#1 342.23,3089.91 r90 top value=0
R82 "FC0402E50R0BST1" 0402L 827.69,3295.33 r180 top value=50
R83 "CRCW06030000Z0EA" 0603 1313.71,3283.79 r180 bottom value=0
R84 "CRCW04020000Z0ED" 0402#1 342.23,3532.91 r270 top value=0
R85 "CRCW06030000Z0EA" 0603L 1116.6,3474.97 r270 bottom value=0
R86 "FC0402E50R0BST1" 0402L 827.69,3327.7 r180 top value=50
R87 "CRCW06030000Z0EA" 0603L 881.7,3442.35 r270 bottom value=0
R88 "CRCW06030000Z0EA" 0603L 1012.37,3475.05 r270 bottom value=0
R89 "CRCW06030000Z0EA" 0603 674.65,3052.05 r270 top value=0
R90 "CRCW0603100KJNEA" 0603 1261.7,3147.35 r180 top value=100k
R91 "CRCW06030000Z0EA" 0603 1158.6,2977.35 r270 top value=0
R92 "CRCW04020000Z0ED" 0402#1 341.65,4533.93 r270 top value=0
R93 "FC0402E50R0BST1" 0402L 967.65,3440.23 r270 top value=50
R94 "RC0603JR-07270RL" 0603 1361.7,3502.35 r45 top value=270
R95 "CRCW06030000Z0EA" 0603 1314.8,3548.35 r45 top value=0
R96 "CRCW0603120RJNEA" 0603 1361.6,3686.97 r45 top value=120
R97 "FC0402E50R0BST1" 0402L 935.28,3440.23 r90 top value=50
R98 "CRCW04020000Z0ED" 0402#1 341.65,4090.93 r90 top value=0
R99 "CRCW04020000Z0ED" 0402#1 865.62,3134.62 r0 bottom value=0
